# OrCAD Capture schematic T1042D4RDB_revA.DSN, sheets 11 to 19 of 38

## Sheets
11 11 QE: size B
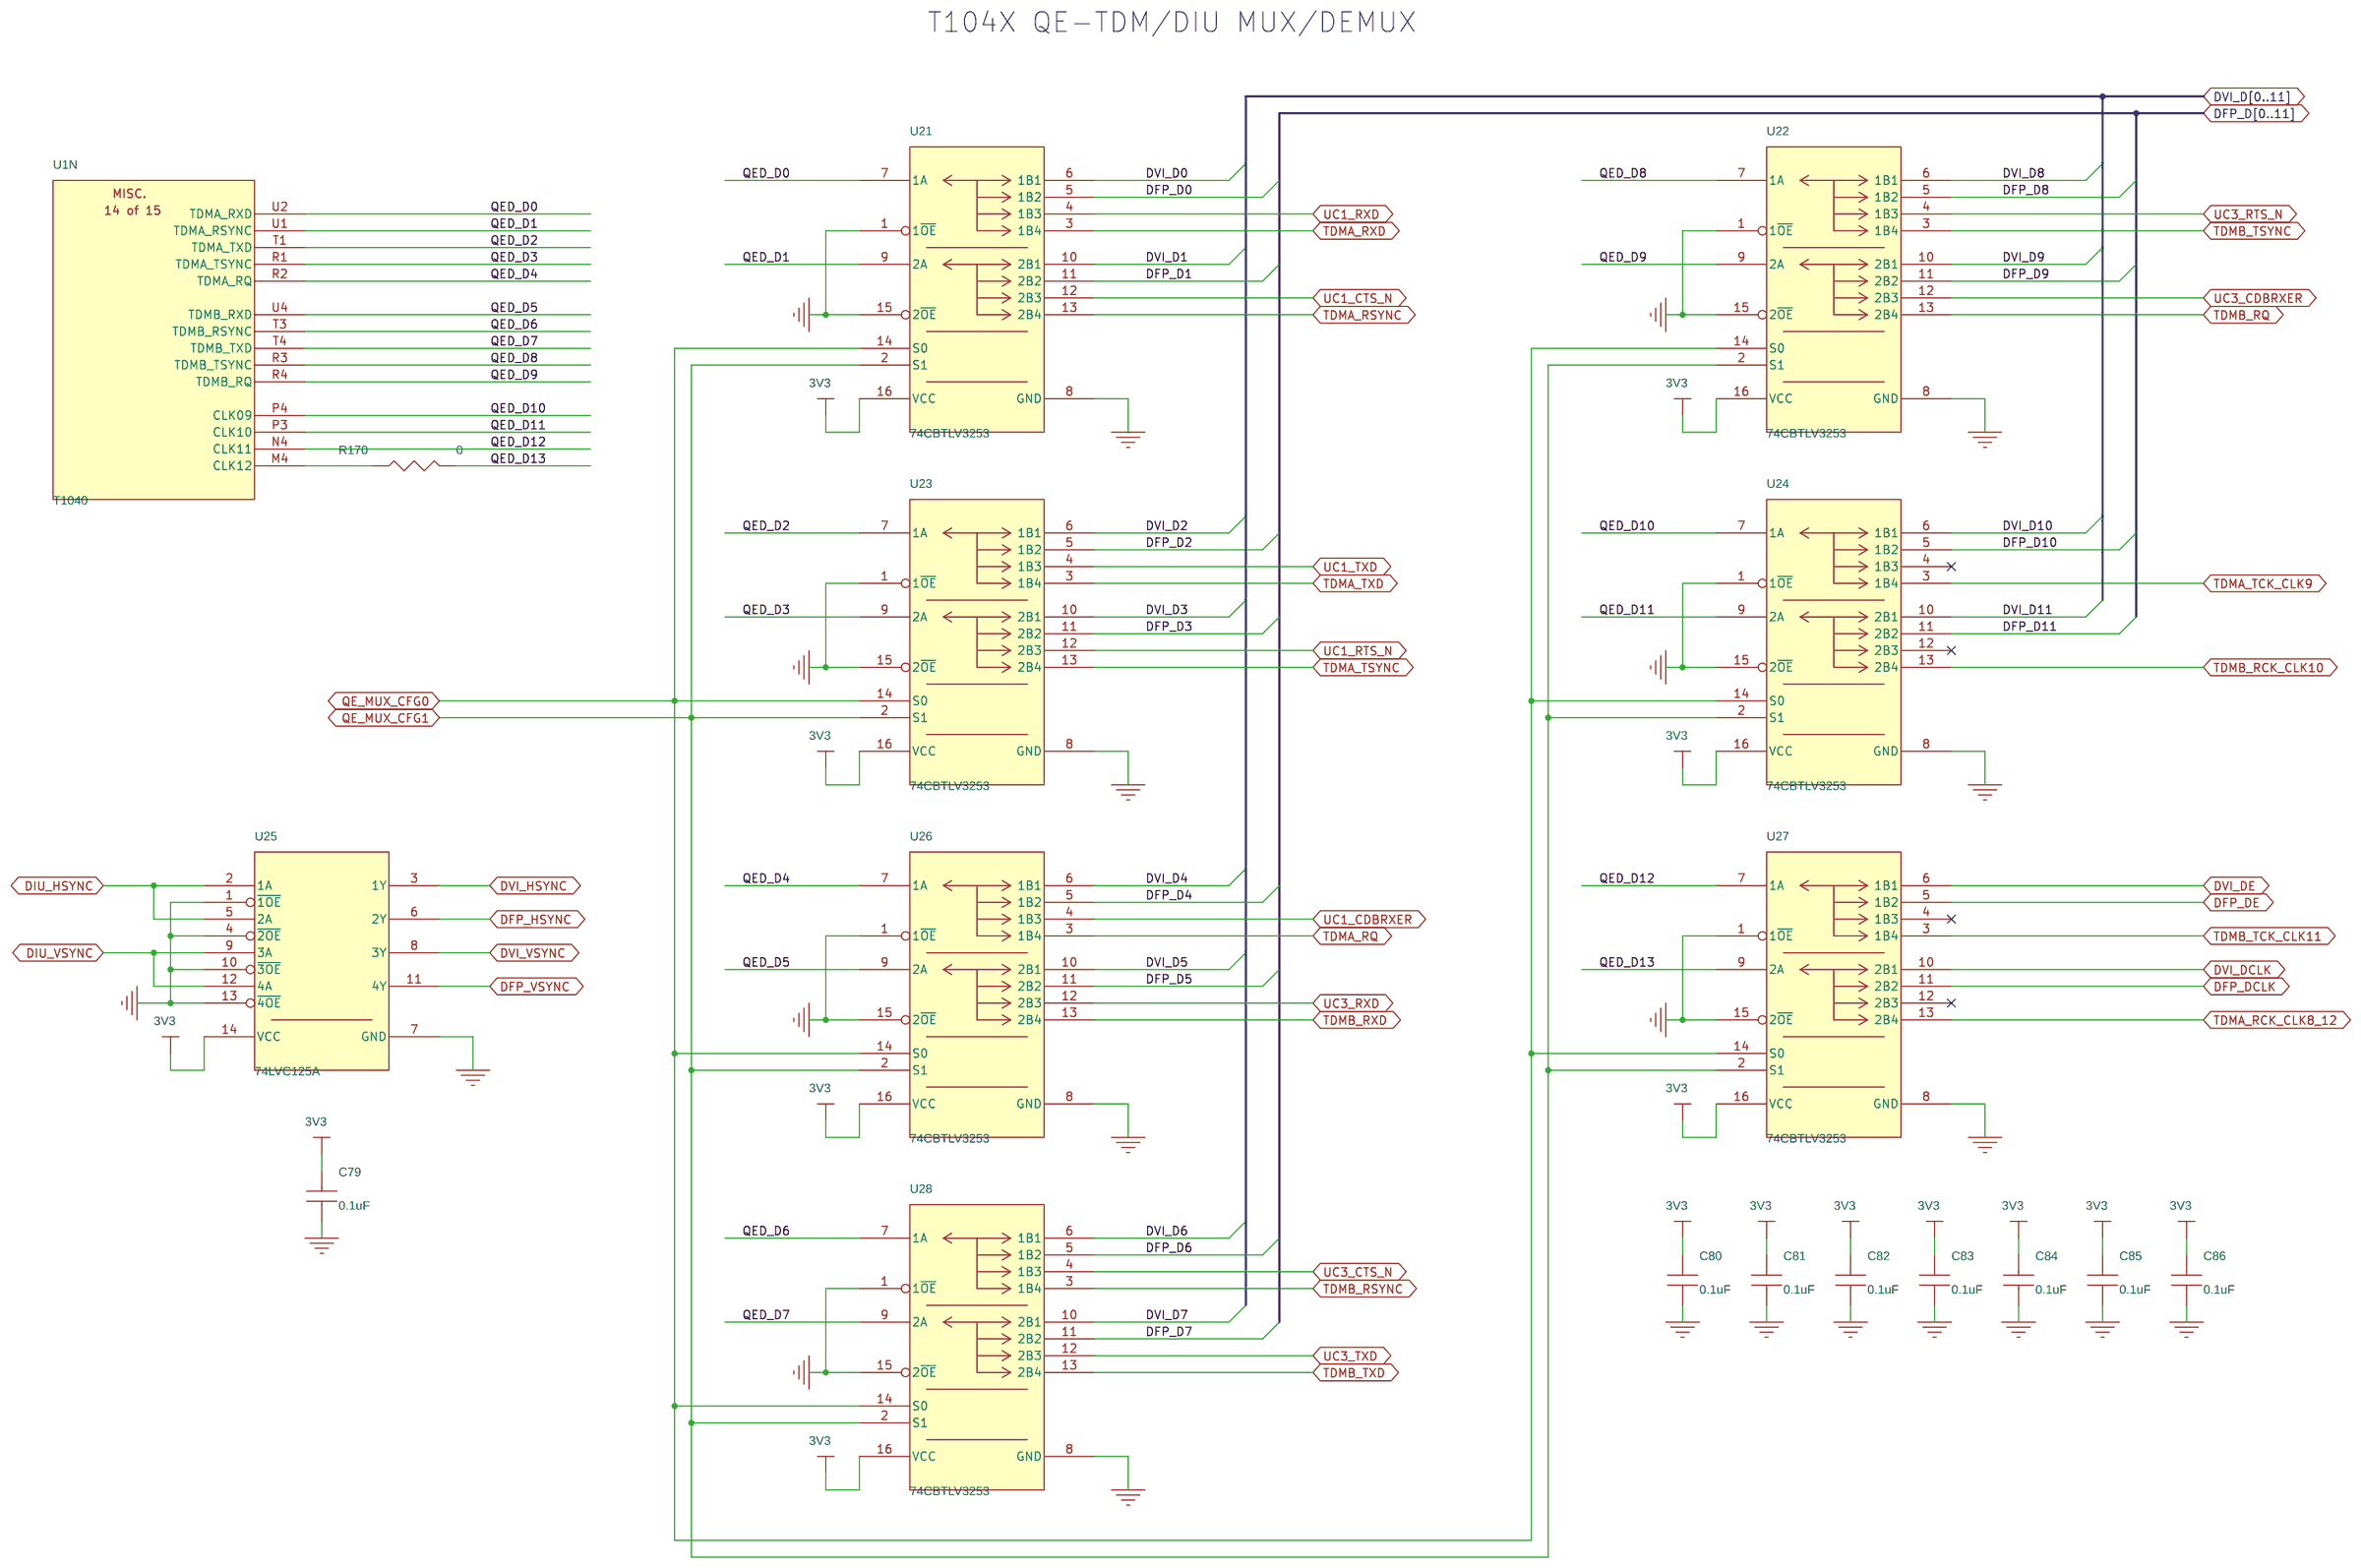
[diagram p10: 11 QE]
12 12 Proc Pwr: size B
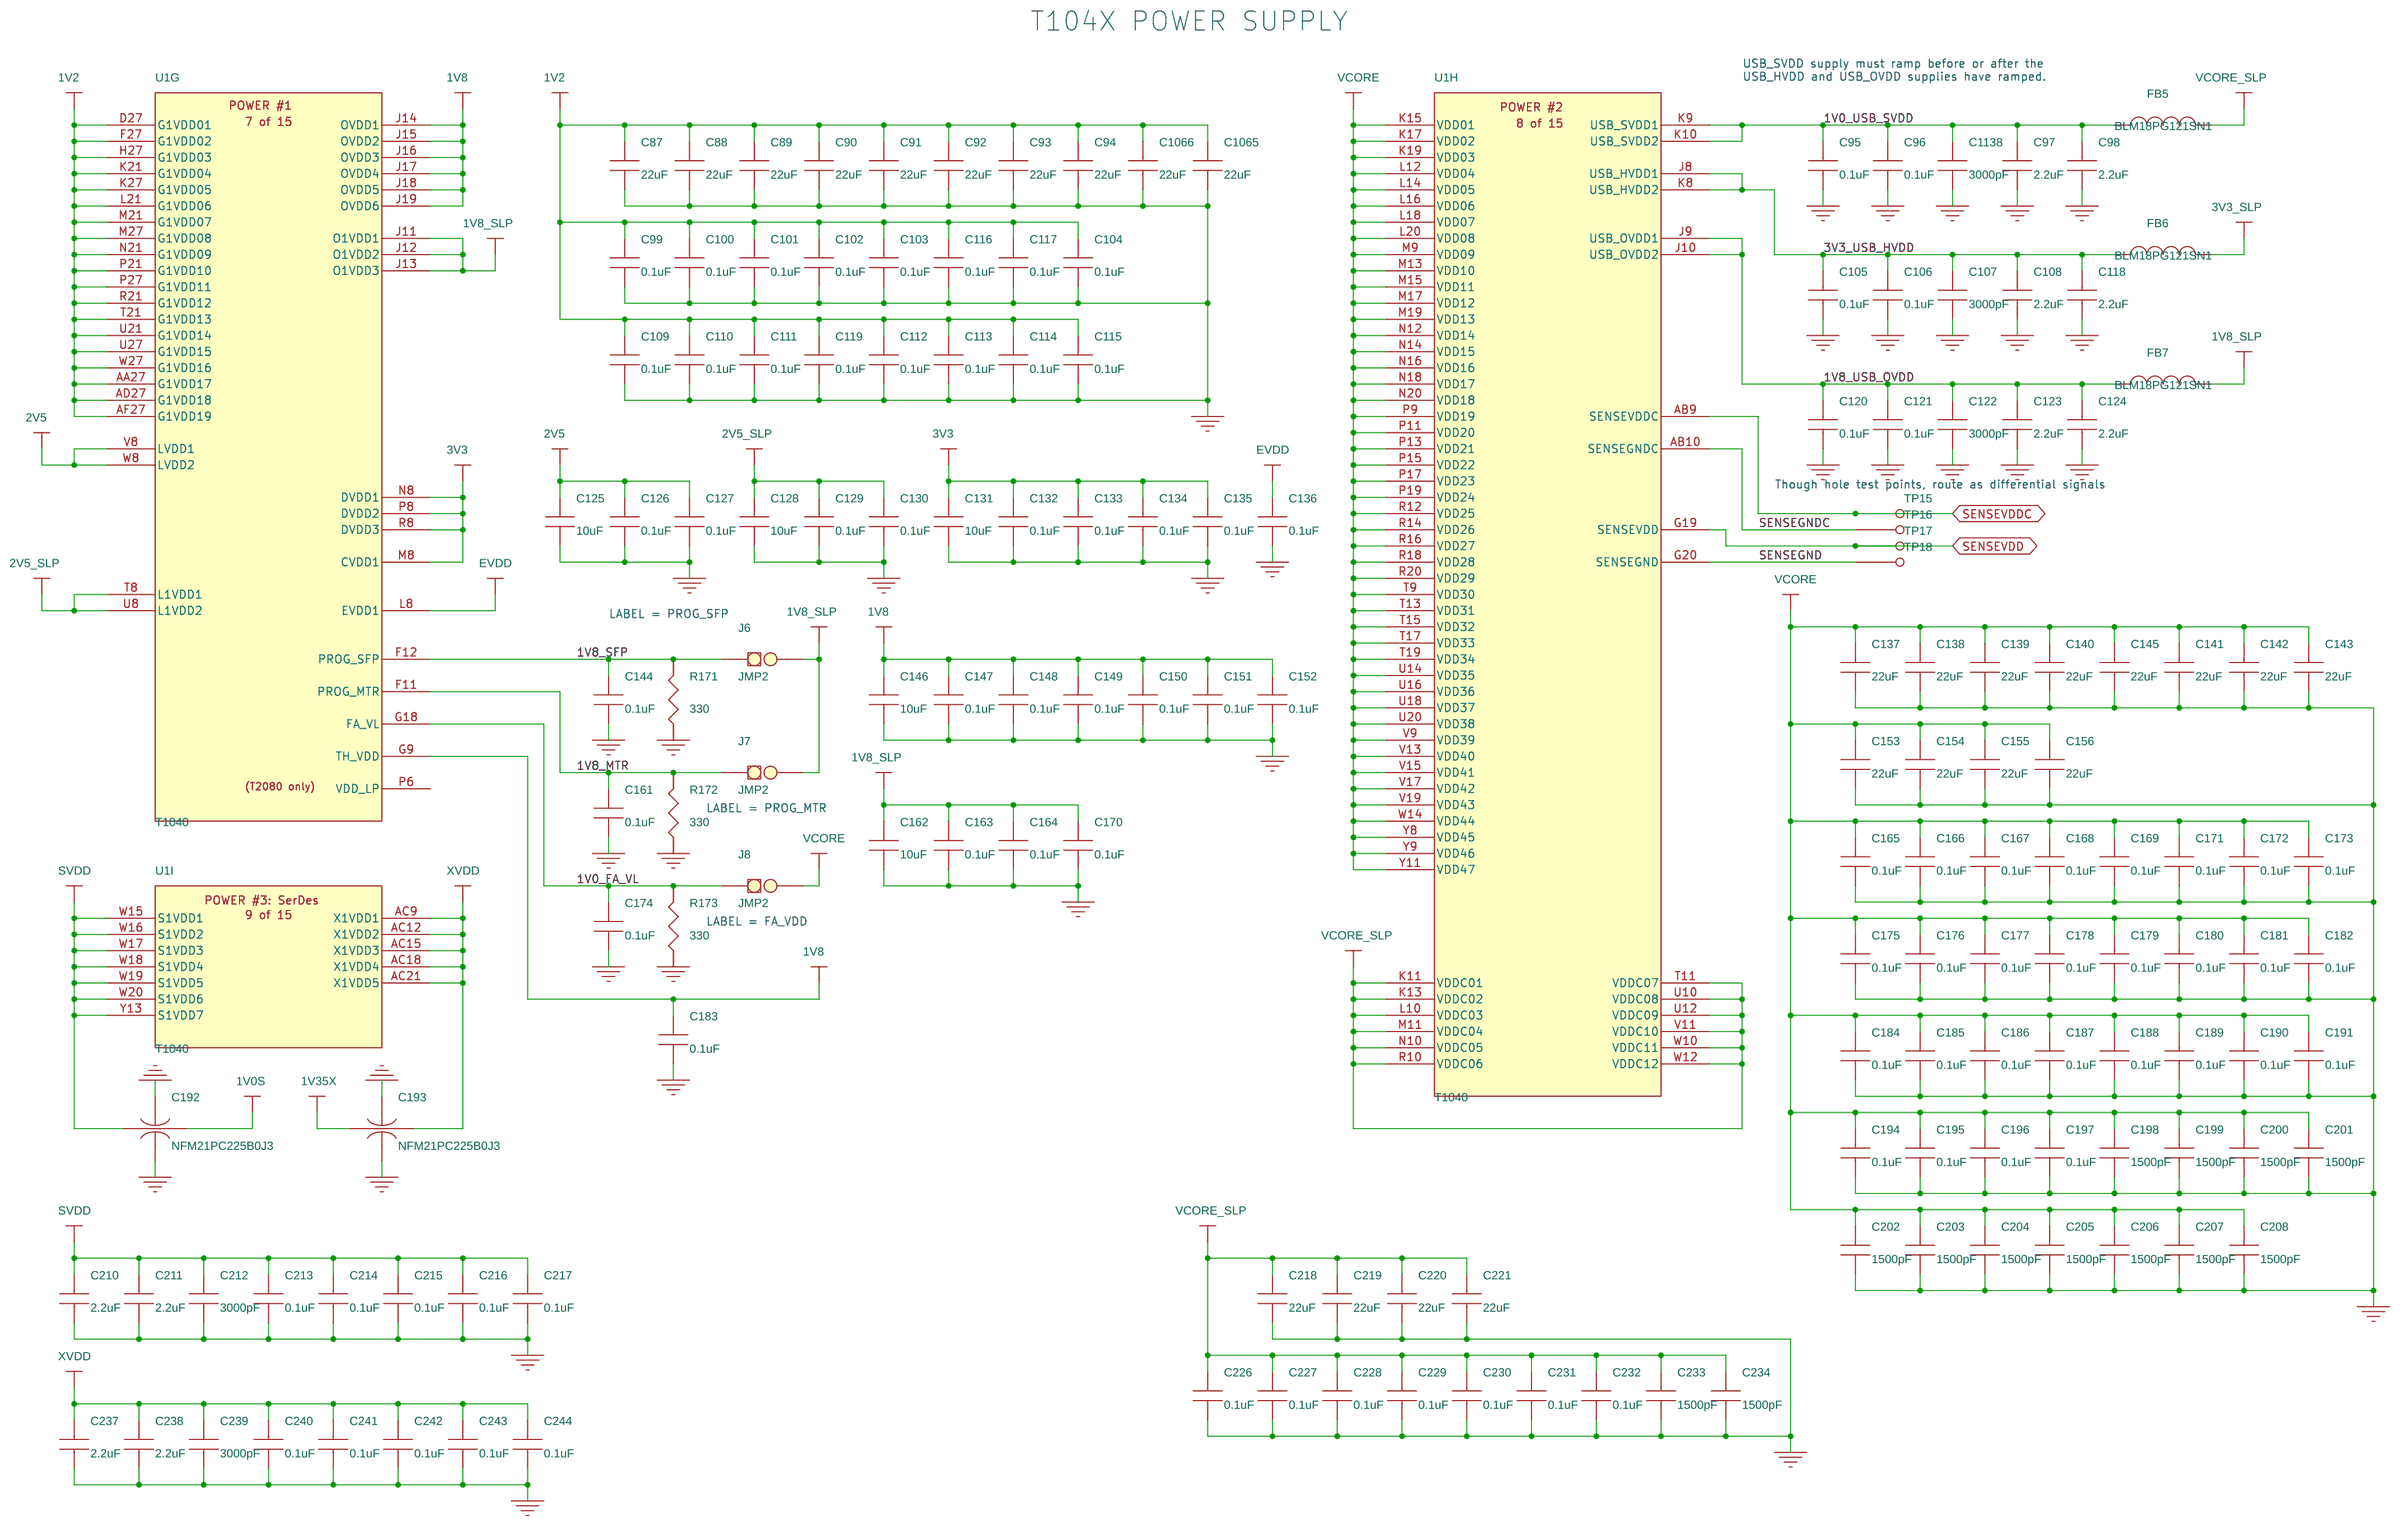
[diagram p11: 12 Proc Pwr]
13 13 Proc Gnd: size B
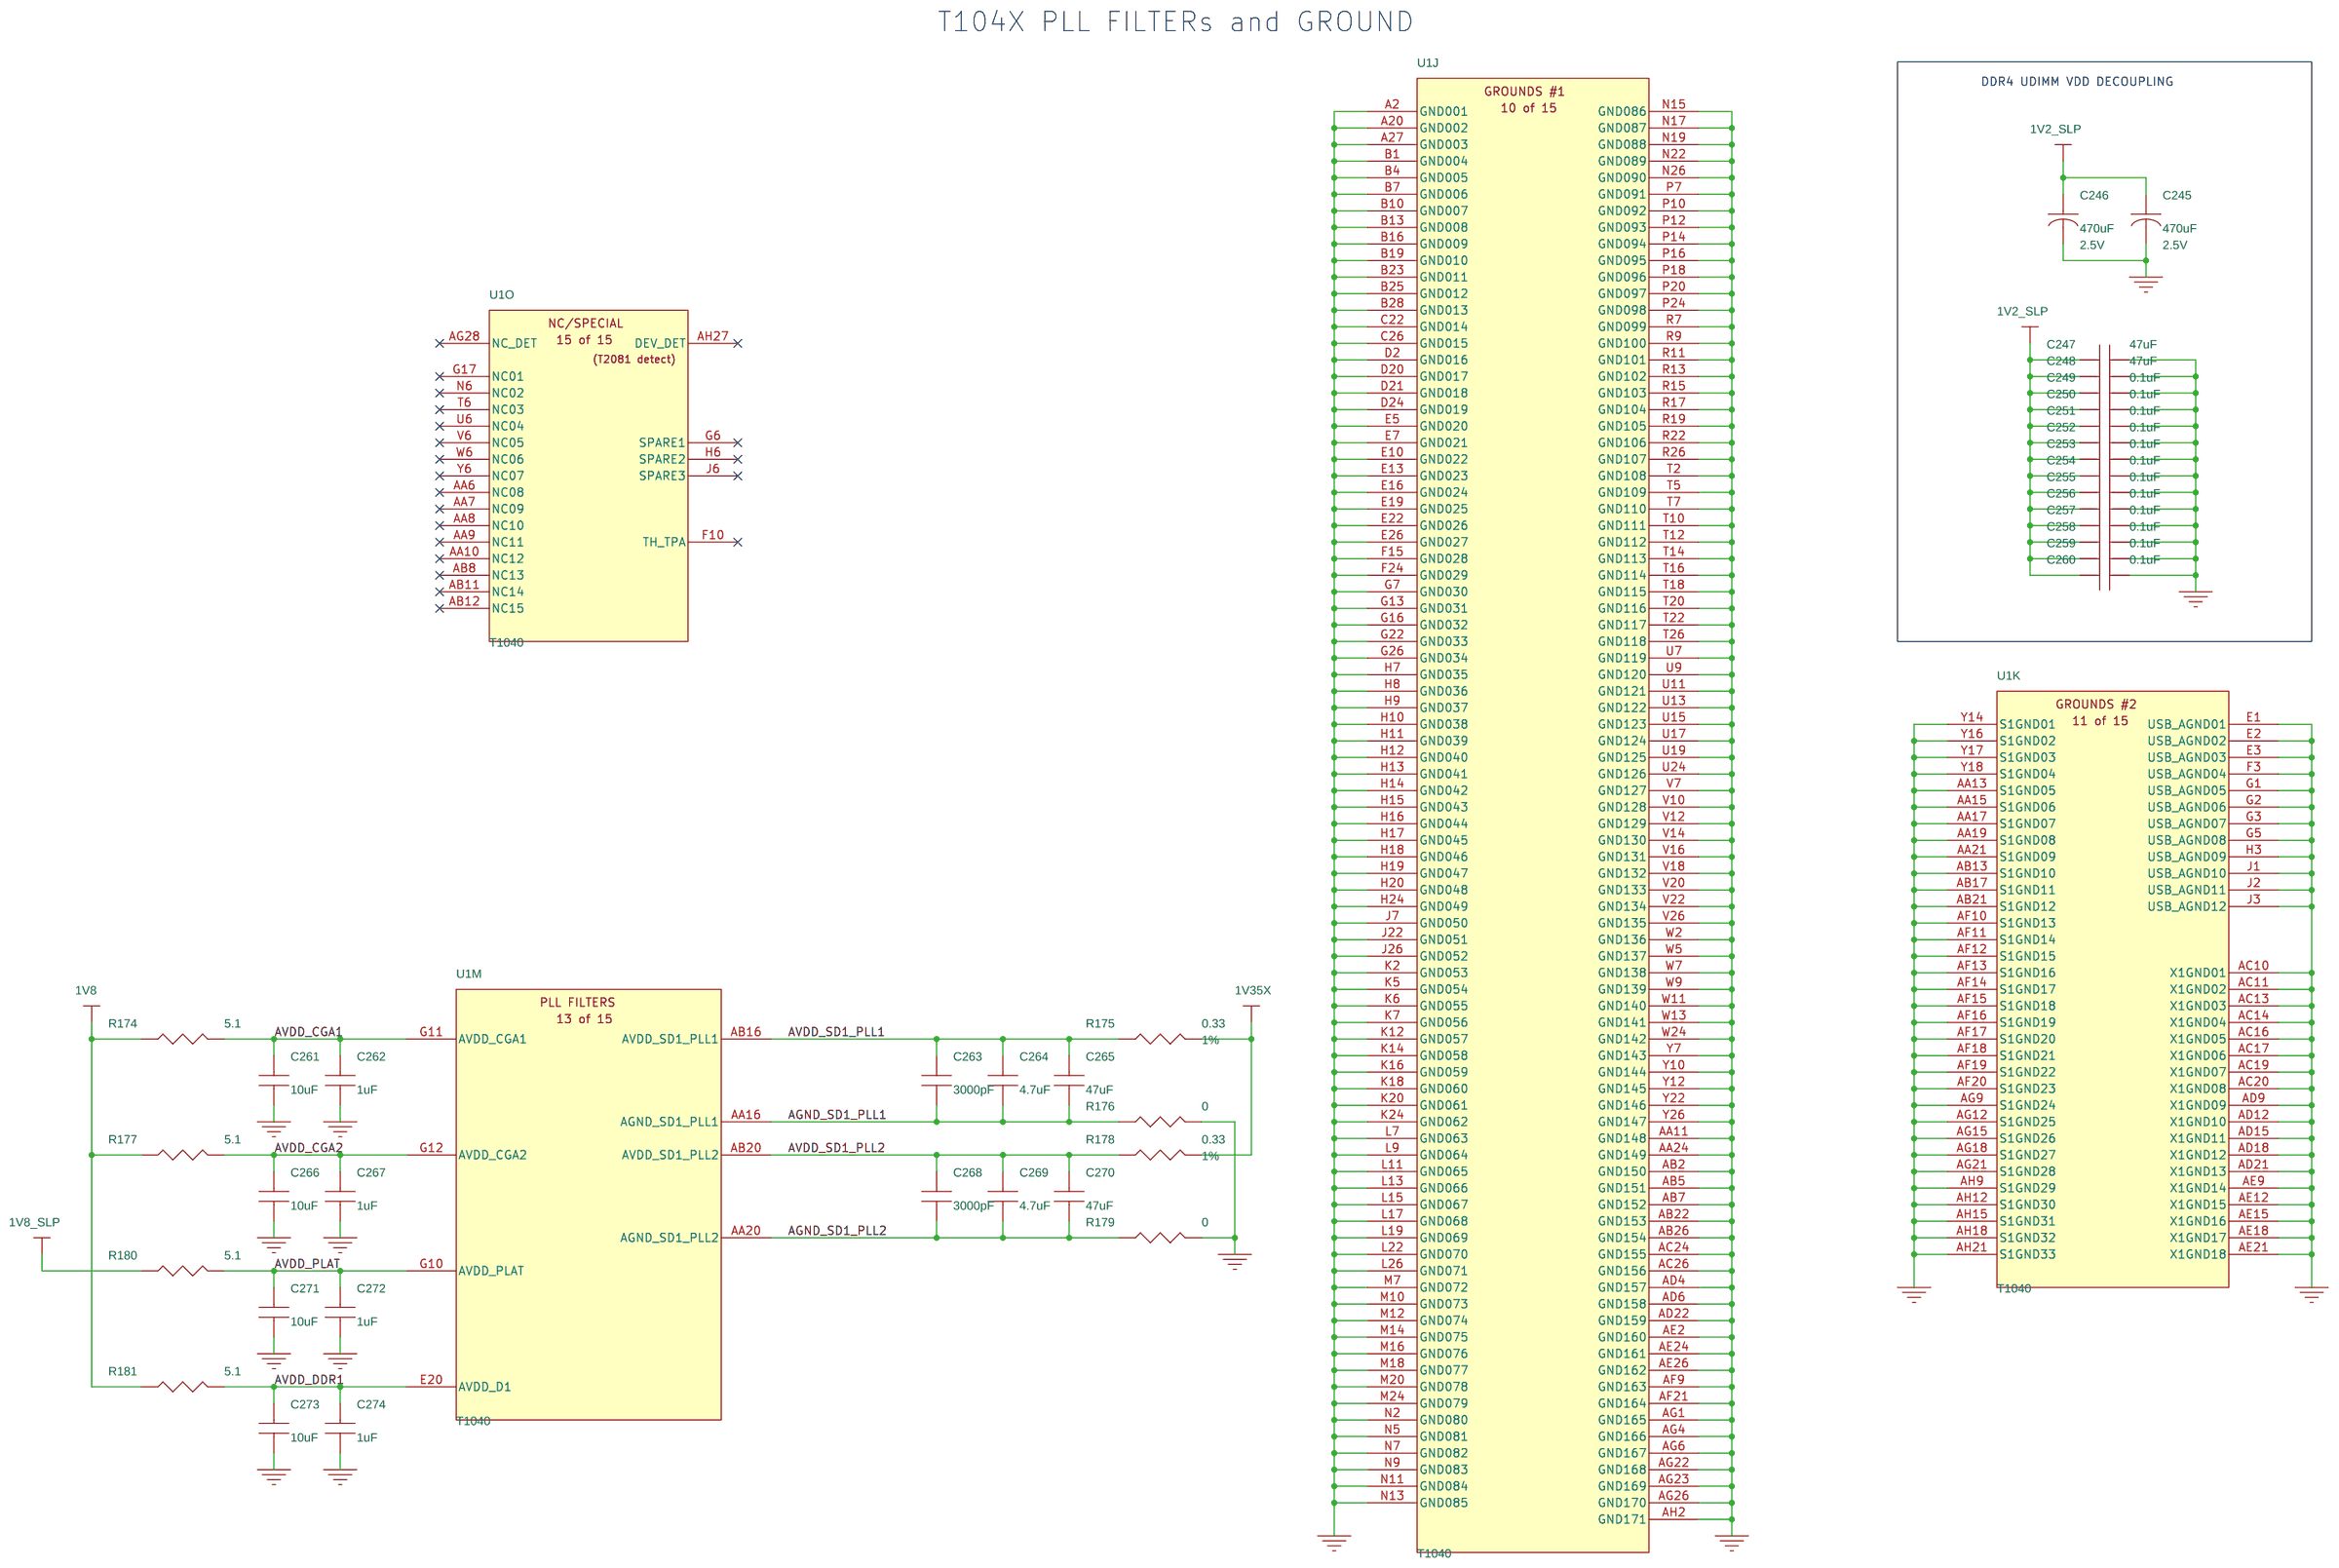
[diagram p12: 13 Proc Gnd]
14 14 UART&I2C: size B
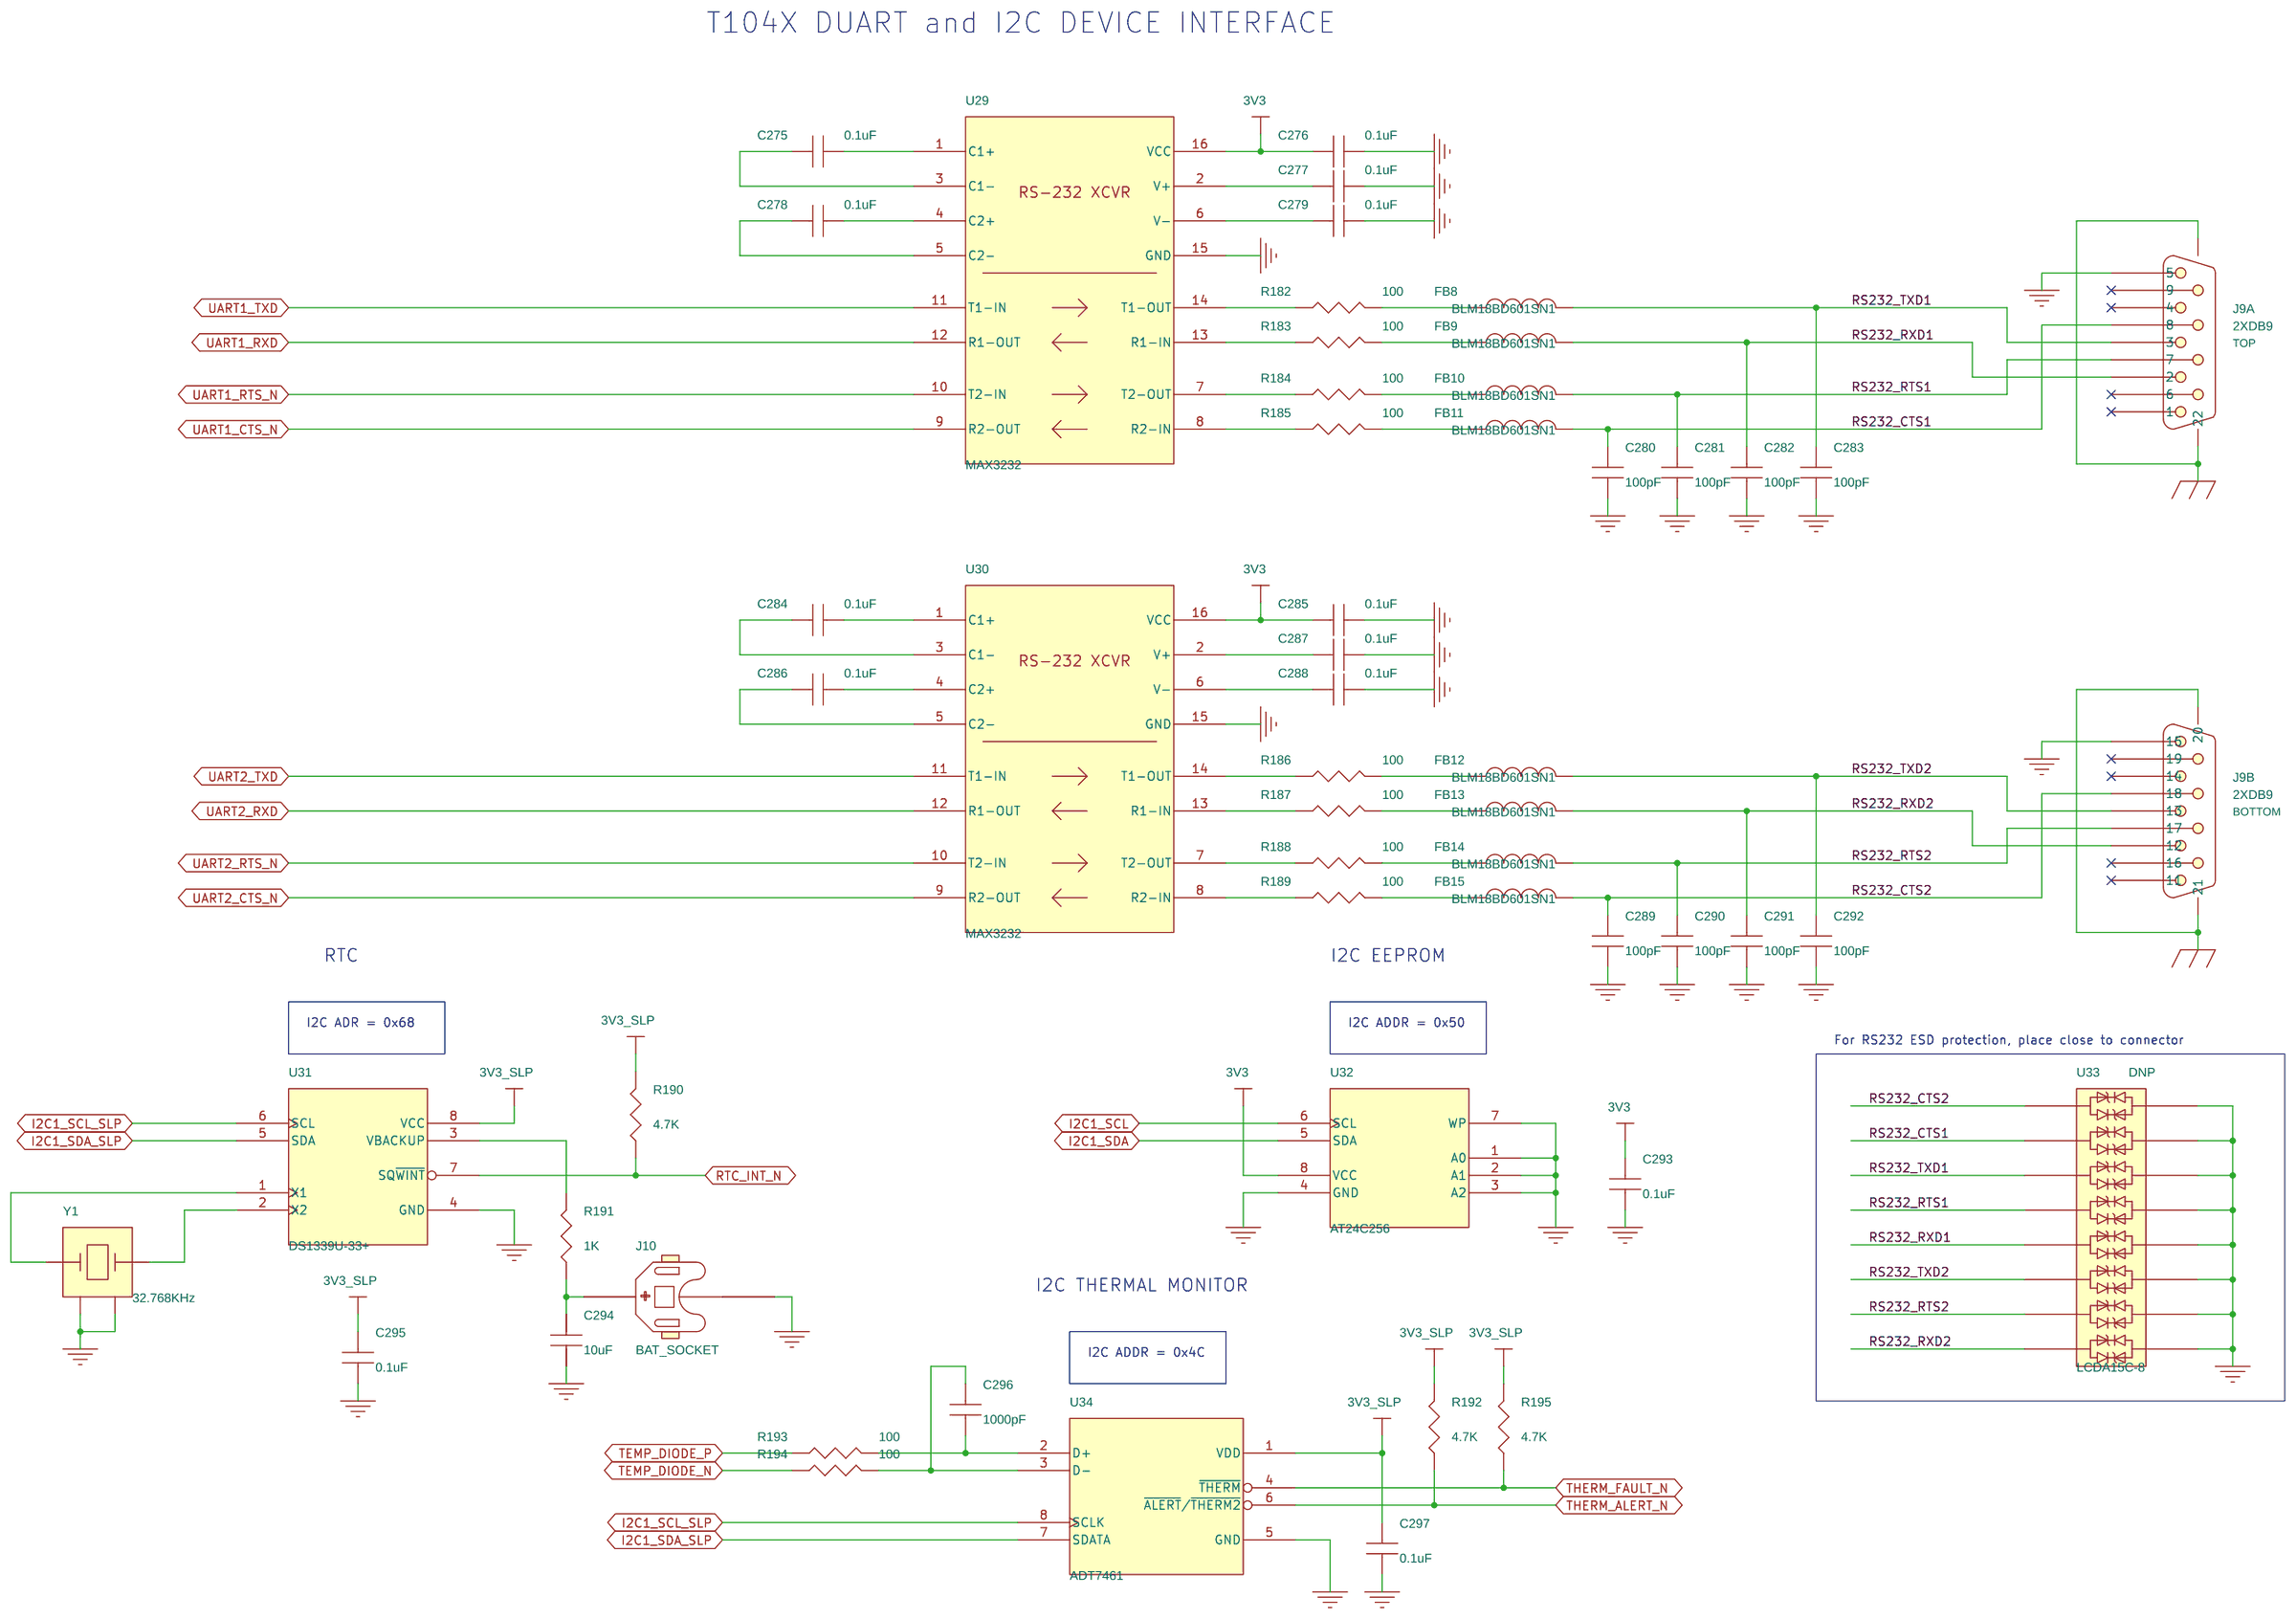
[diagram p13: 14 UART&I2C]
15 15 TDM: size B
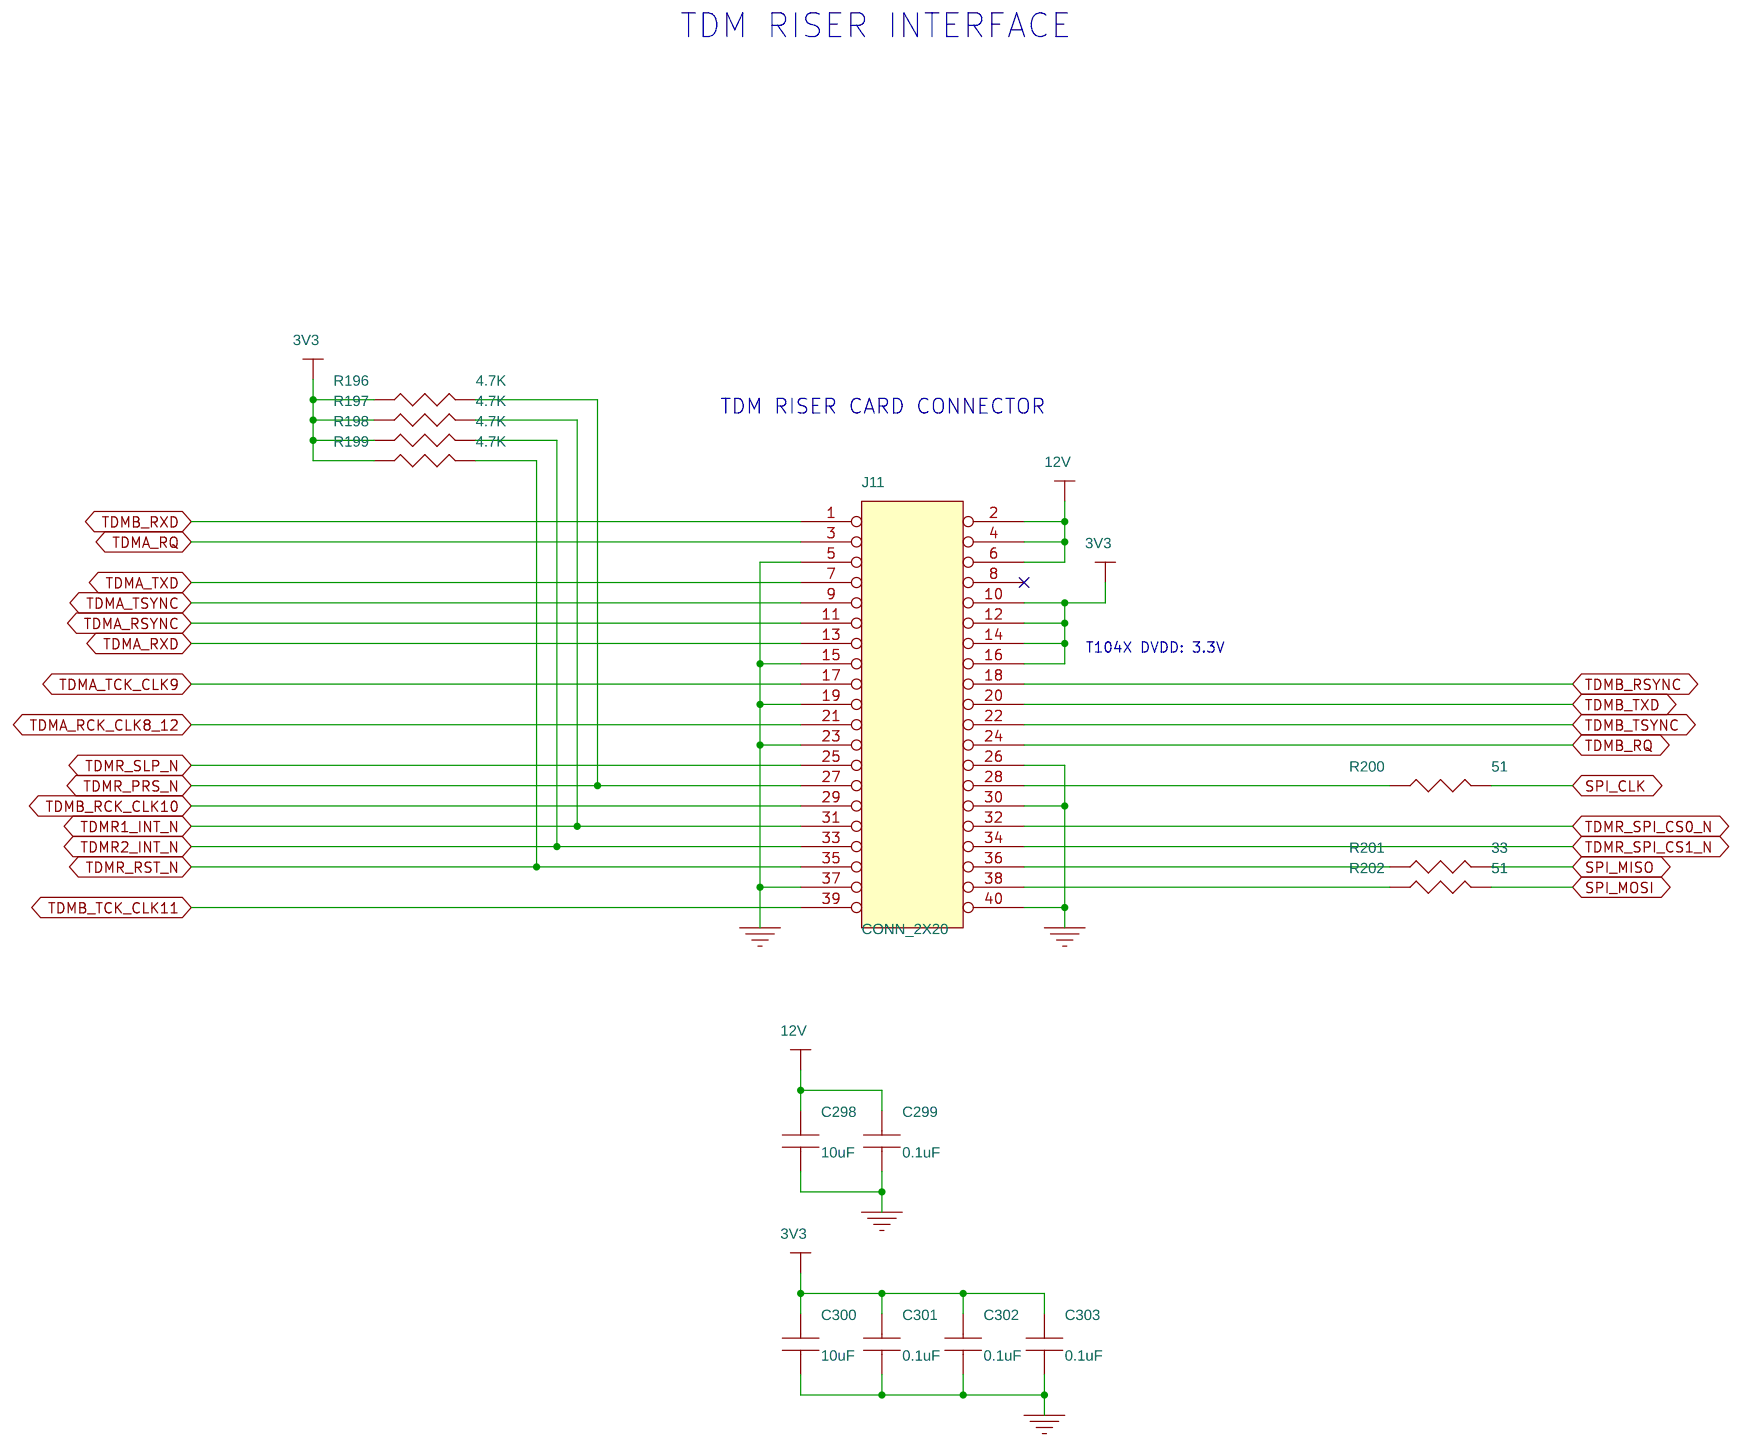
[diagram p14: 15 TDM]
16 16 HDMI: size B
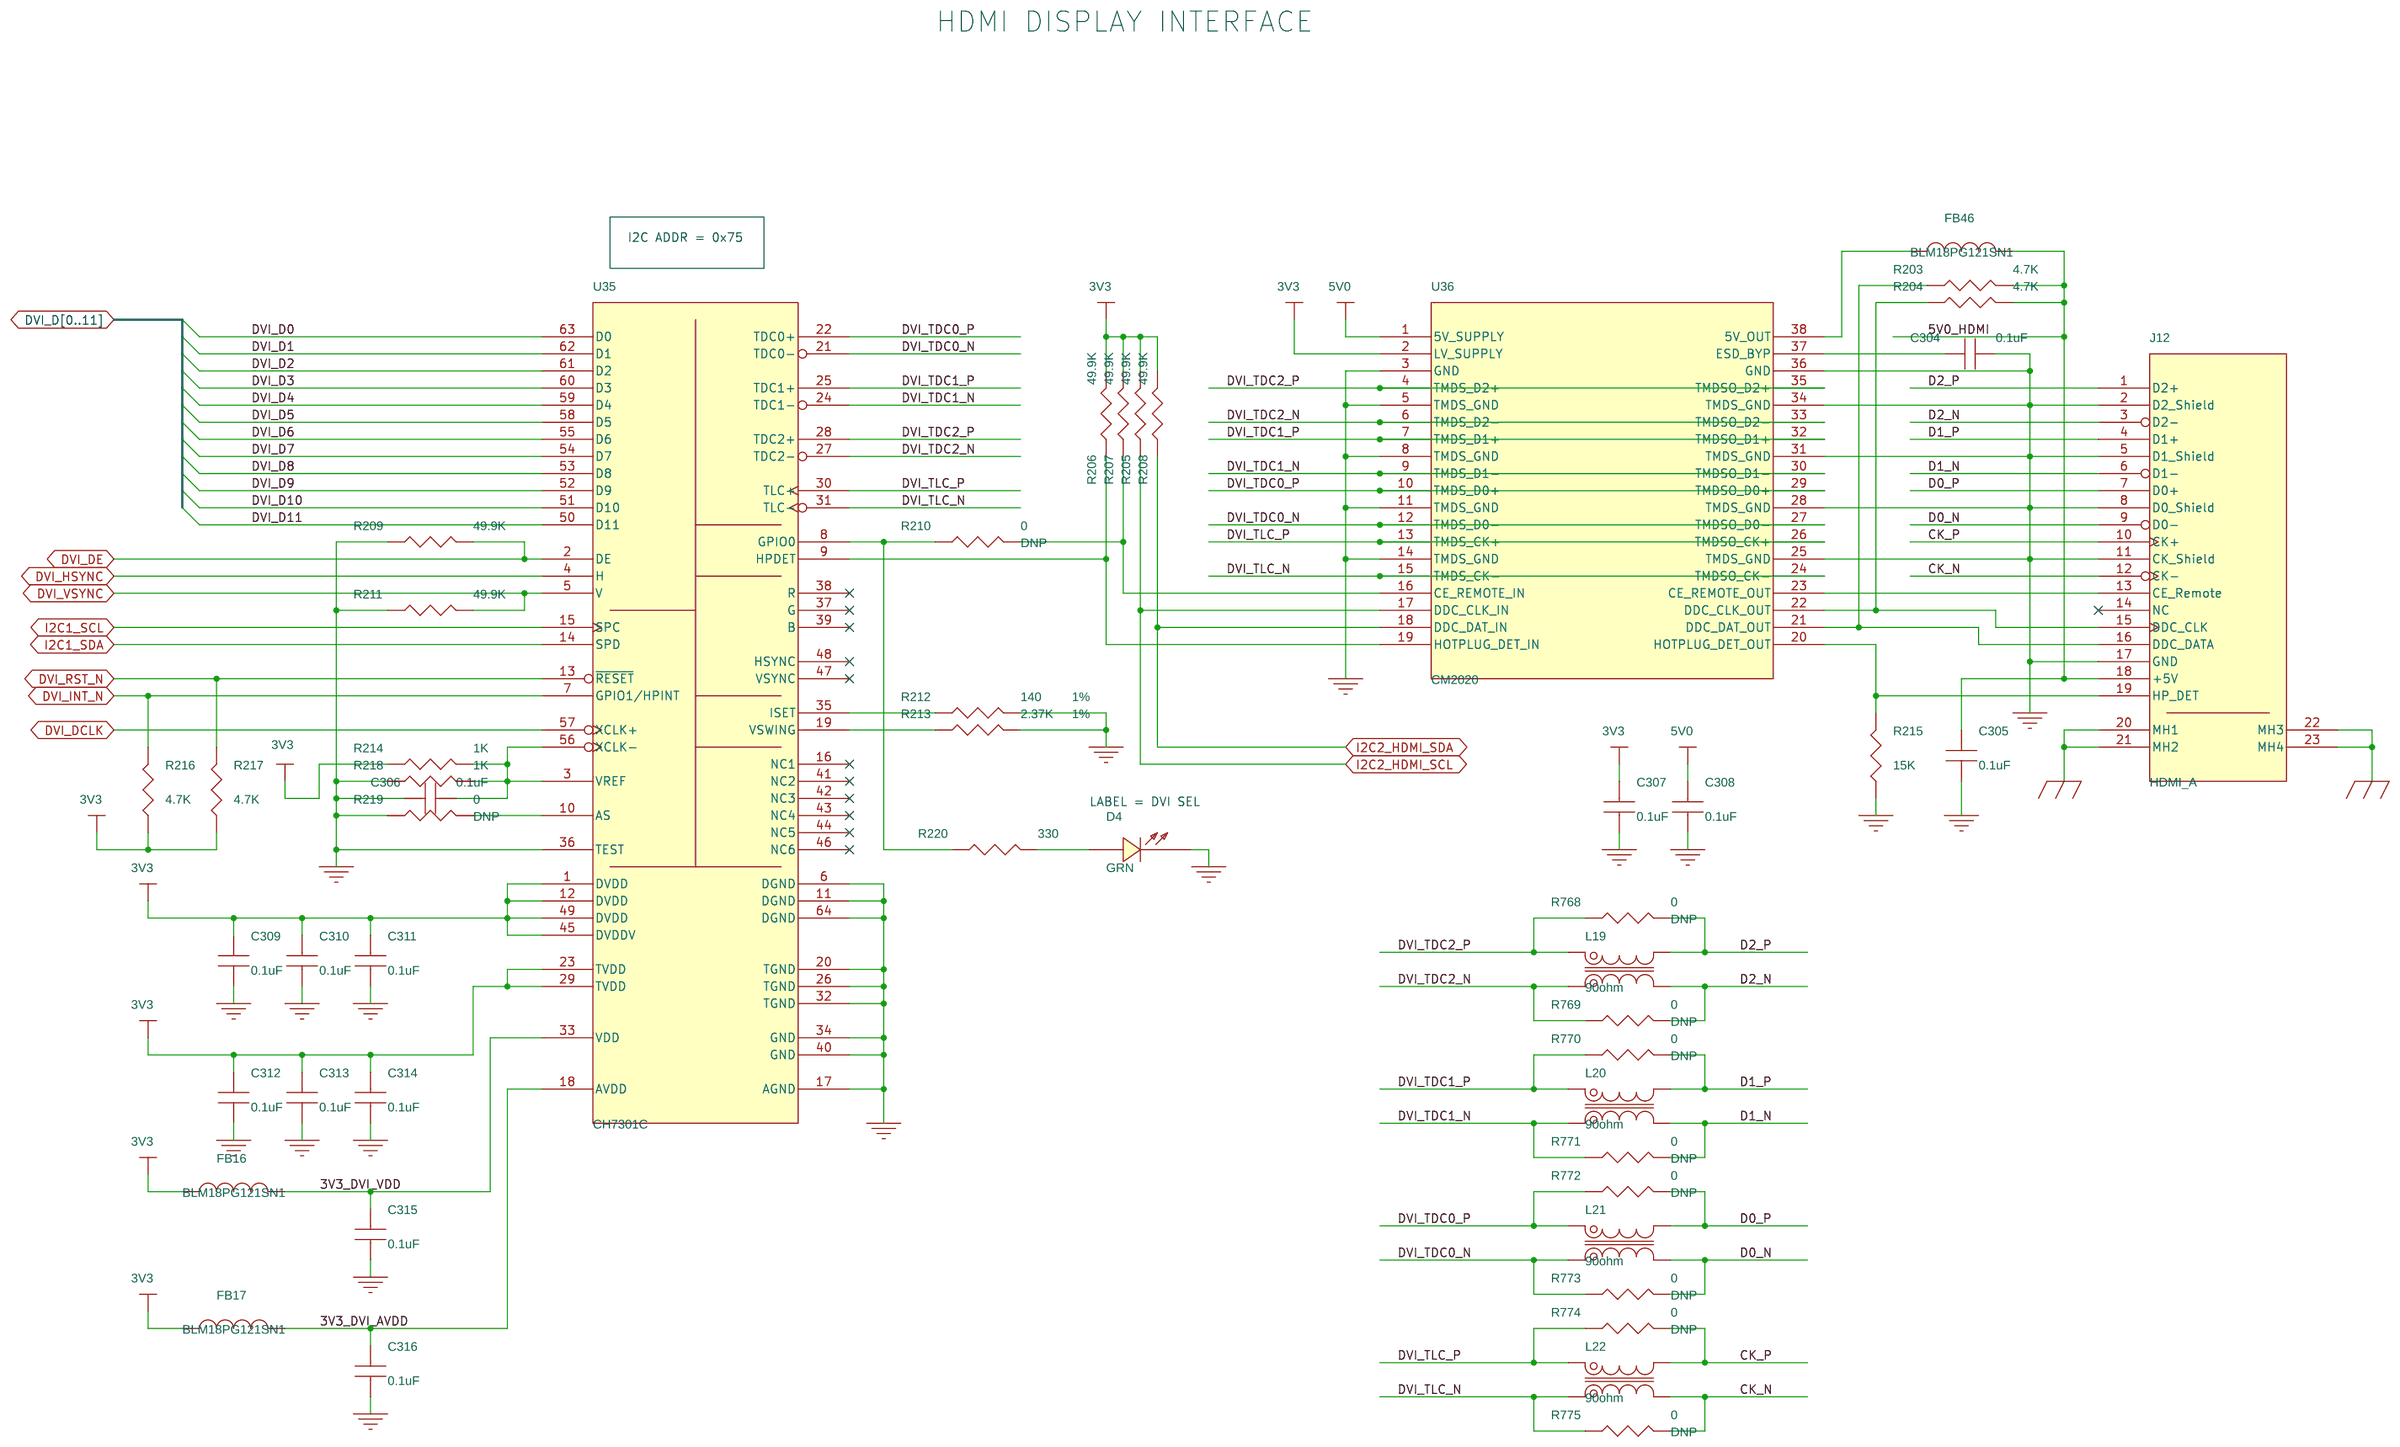
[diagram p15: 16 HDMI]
17 17 LCD: size B
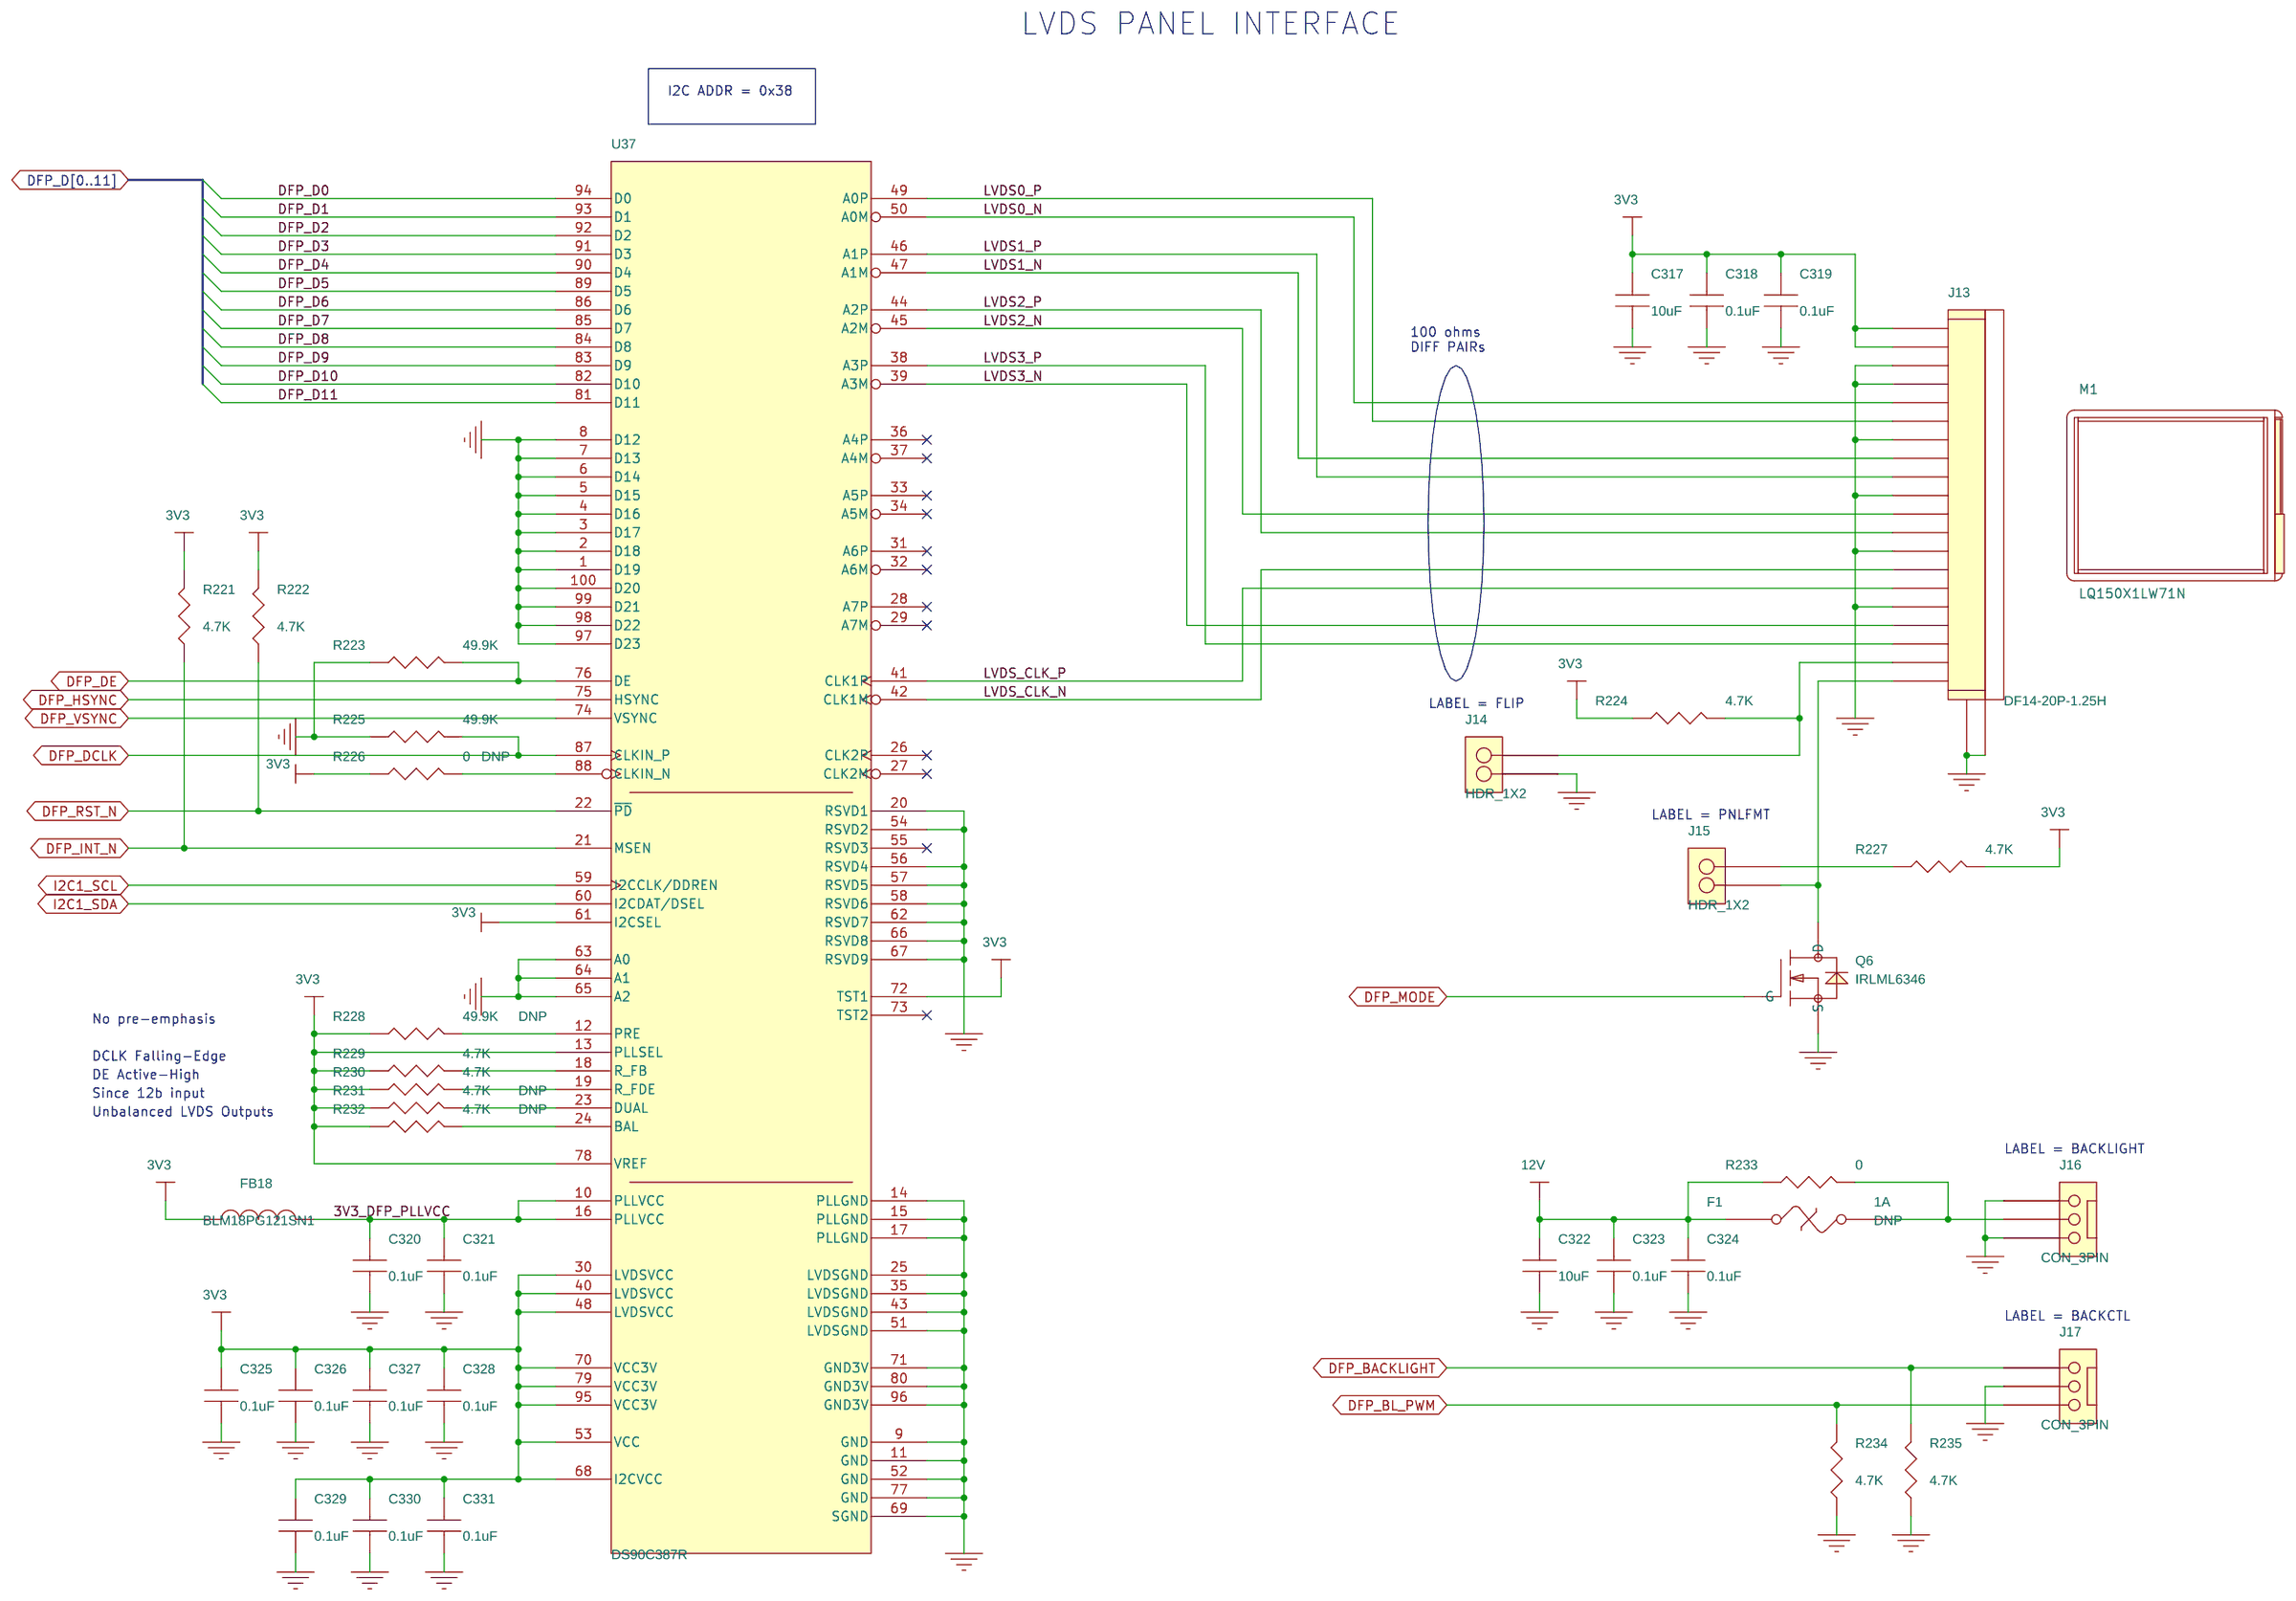
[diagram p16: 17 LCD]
18 18 Profibus: size B
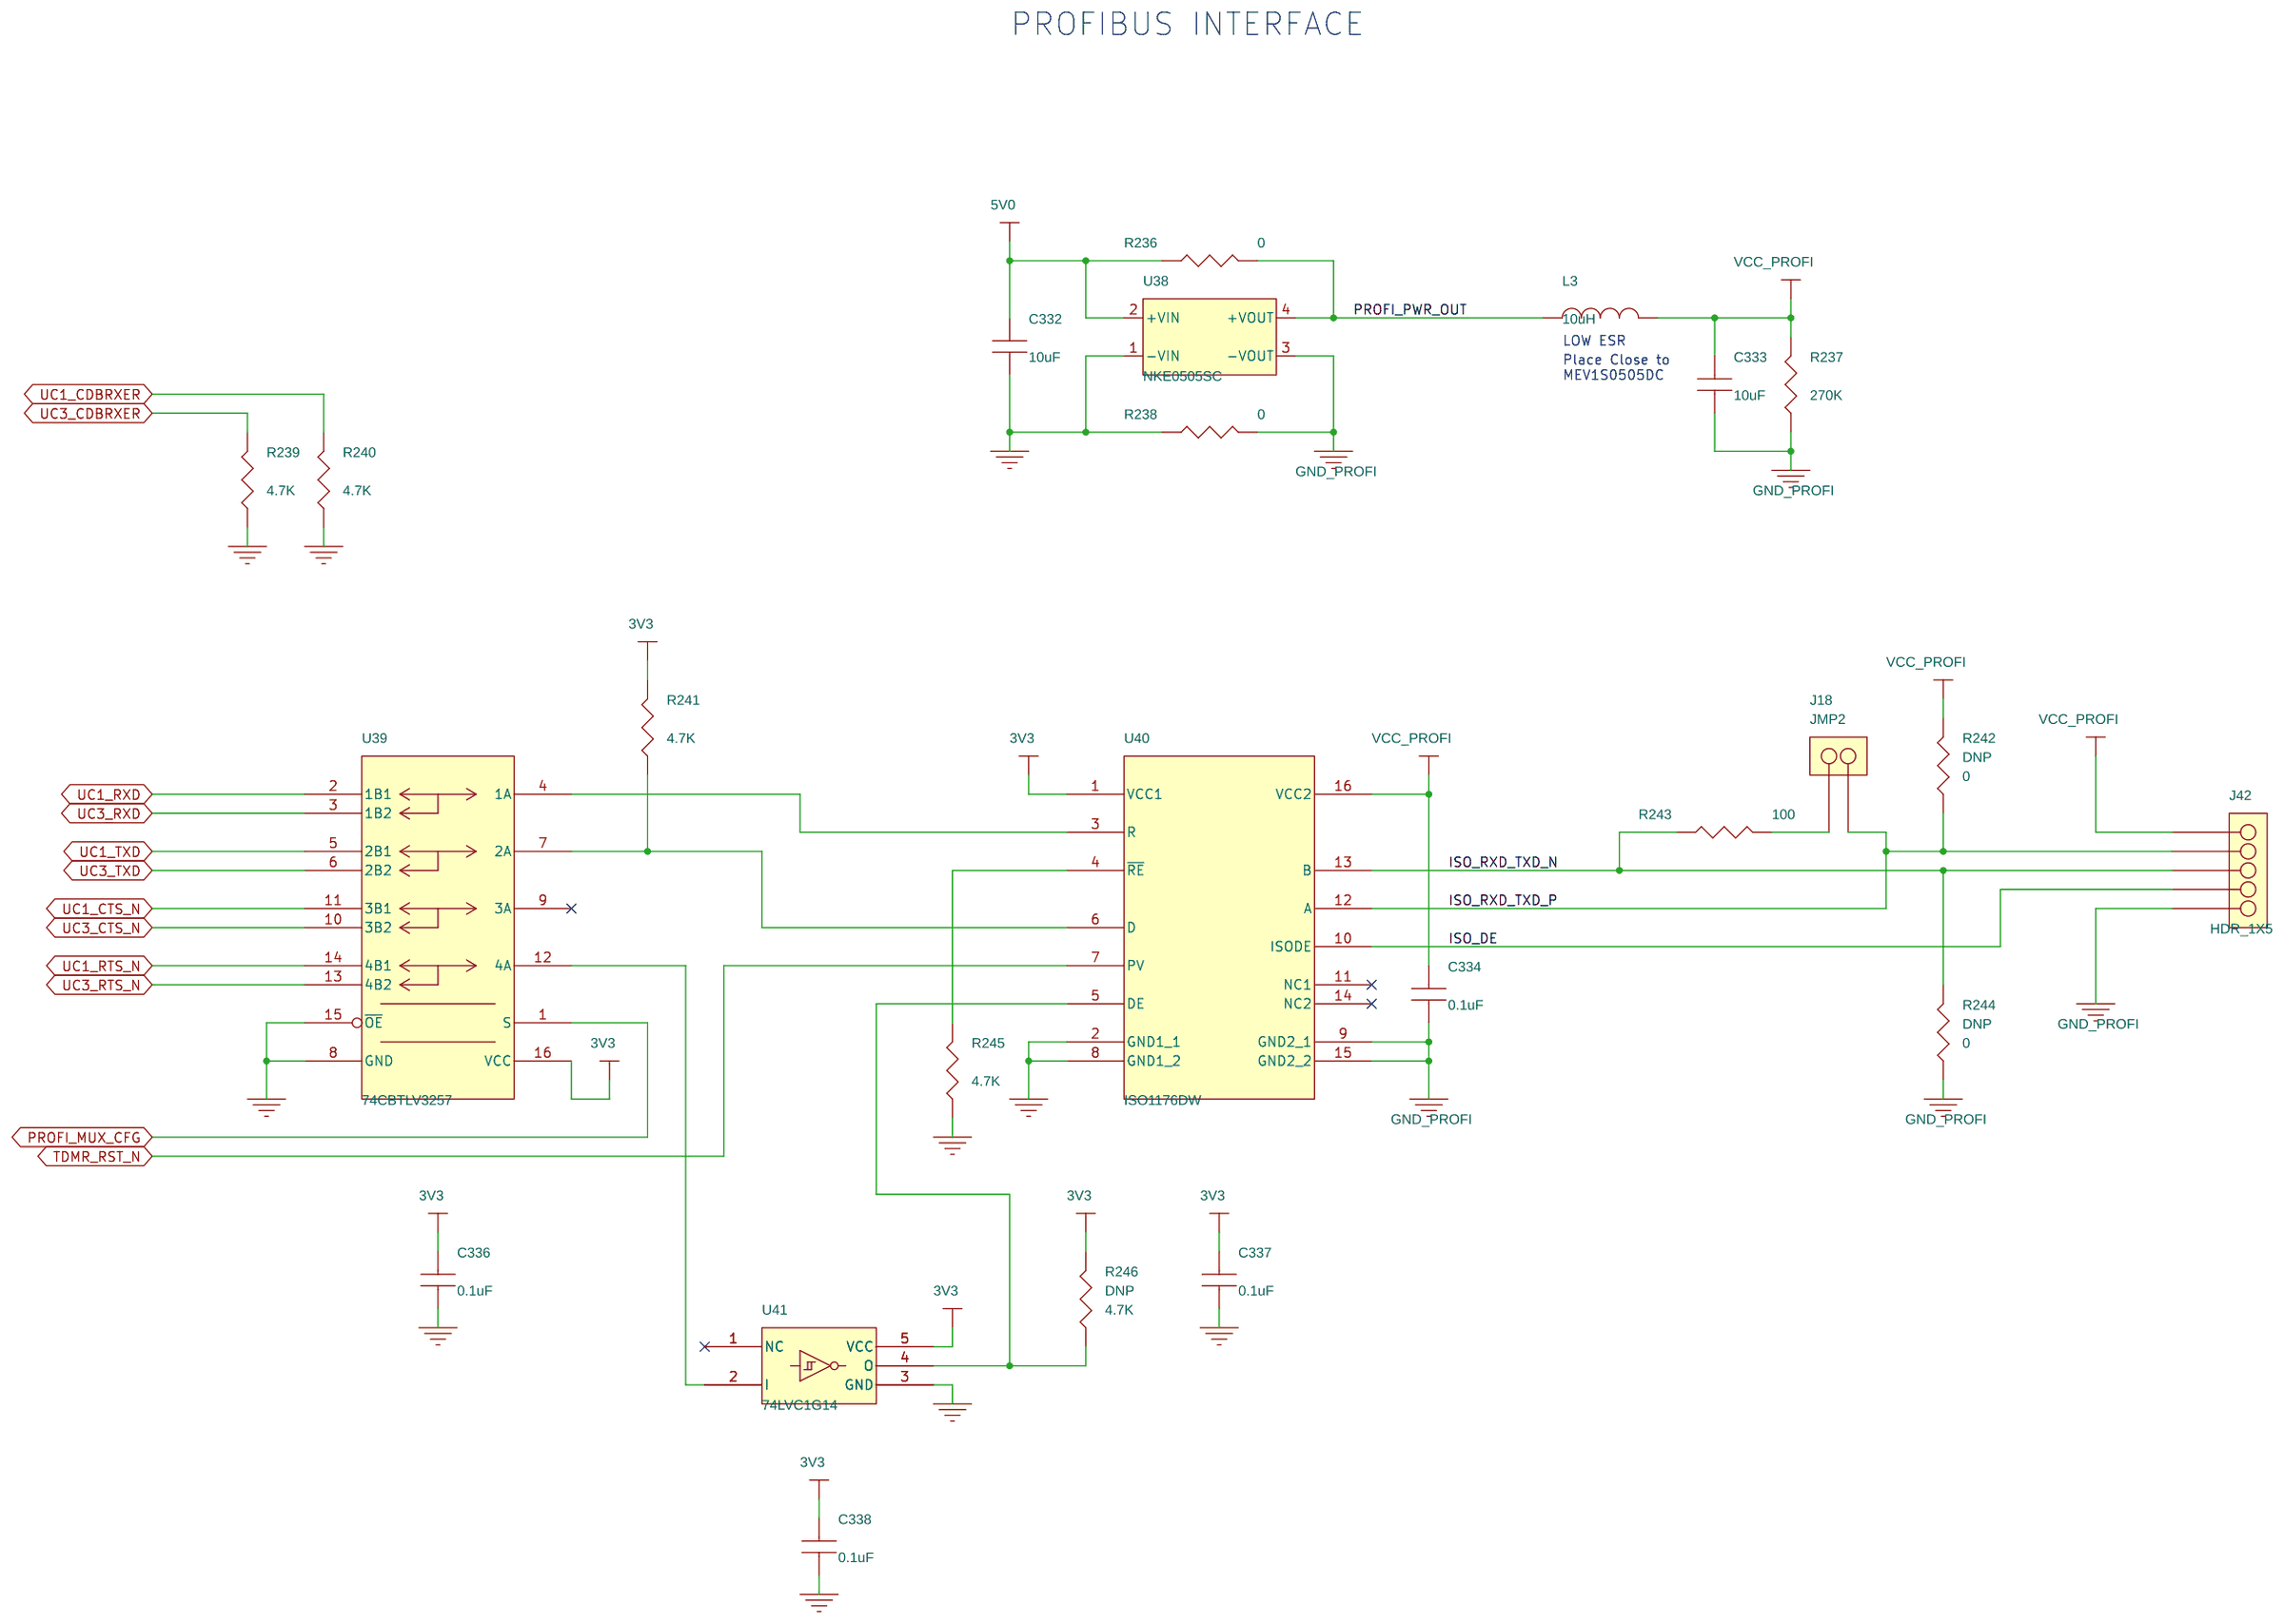
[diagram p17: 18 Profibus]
19 19 EC1 PHY: size B
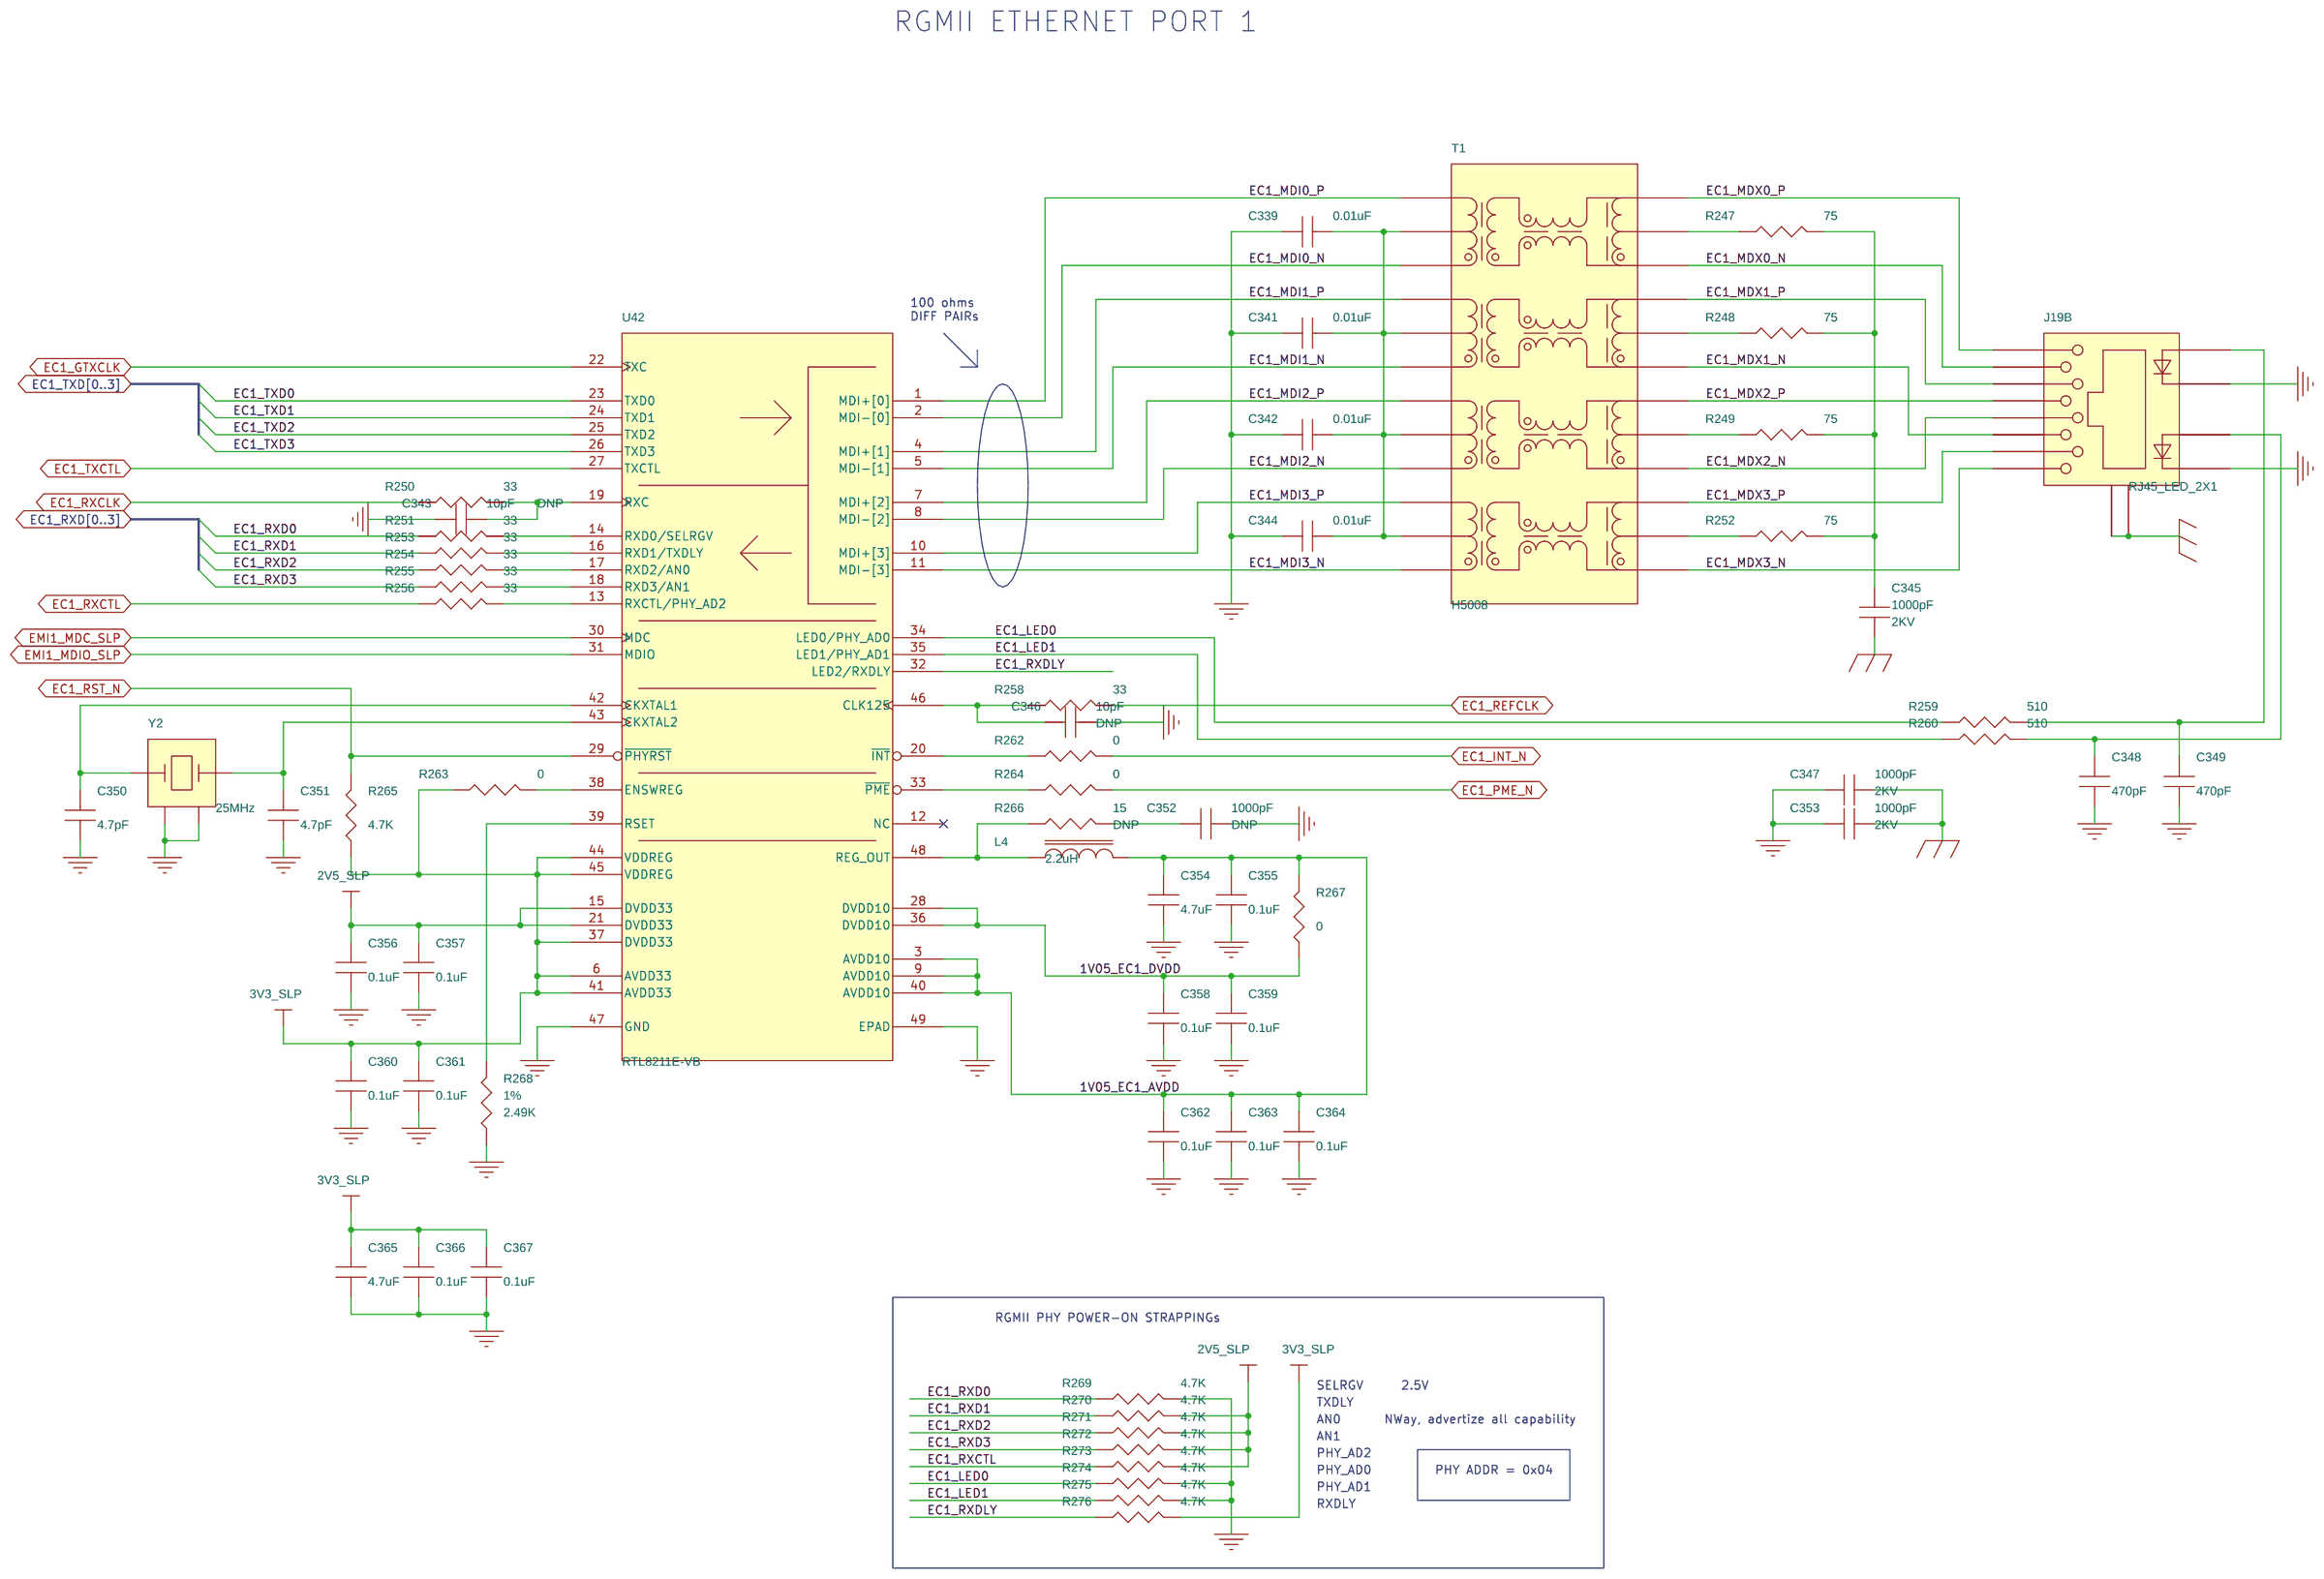
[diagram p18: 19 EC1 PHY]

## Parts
sheet 07 SYS
U1  T1040  [bga_p080_780]  (sections A,B,C,D,E,F,G,H,I,J,K,L,M,N,O)
sheet 11 QE
C79  0.1uF  [0402]
C80  0.1uF  [0402]
C81  0.1uF  [0402]
C82  0.1uF  [0402]
C83  0.1uF  [0402]
C84  0.1uF  [0402]
C85  0.1uF  [0402]
C86  0.1uF  [0402]
R170  0  [0402]
U21  74CBTLV3253  [tssop_16]
U22  74CBTLV3253  [tssop_16]
U23  74CBTLV3253  [tssop_16]
U24  74CBTLV3253  [tssop_16]
U25  74LVC125A  [tssop_14]
U26  74CBTLV3253  [tssop_16]
U27  74CBTLV3253  [tssop_16]
U28  74CBTLV3253  [tssop_16]
sheet 12 Proc Pwr
C87  22uF  [0805]
C88  22uF  [0805]
C89  22uF  [0805]
C90  22uF  [0805]
C91  22uF  [0805]
C92  22uF  [0805]
C93  22uF  [0805]
C94  22uF  [0805]
C95  0.1uF  [0201]
C96  0.1uF  [0201]
C97  2.2uF  [0402]
C98  2.2uF  [0402]
C99  0.1uF  [0201]
C100  0.1uF  [0201]
C101  0.1uF  [0201]
C102  0.1uF  [0201]
C103  0.1uF  [0201]
C104  0.1uF  [0201]
C105  0.1uF  [0201]
C106  0.1uF  [0201]
C107  3000pF  [0402]
C108  2.2uF  [0402]
C109  0.1uF  [0201]
C110  0.1uF  [0201]
C111  0.1uF  [0201]
C112  0.1uF  [0201]
C113  0.1uF  [0201]
C114  0.1uF  [0201]
C115  0.1uF  [0201]
C116  0.1uF  [0201]
C117  0.1uF  [0201]
C118  2.2uF  [0402]
C119  0.1uF  [0201]
C120  0.1uF  [0201]
C121  0.1uF  [0201]
C122  3000pF  [0402]
C123  2.2uF  [0402]
C124  2.2uF  [0402]
C125  10uF  [0603]
C126  0.1uF  [0201]
C127  0.1uF  [0201]
C128  10uF  [0603]
C129  0.1uF  [0201]
C130  0.1uF  [0201]
C131  10uF  [0603]
C132  0.1uF  [0201]
C133  0.1uF  [0201]
C134  0.1uF  [0201]
C135  0.1uF  [0201]
C136  0.1uF  [0201]
C137  22uF  [0805]
C138  22uF  [0805]
C139  22uF  [0805]
C140  22uF  [0805]
C141  22uF  [0805]
C142  22uF  [0805]
C143  22uF  [0805]
C144  0.1uF  [0201]
C145  22uF  [0805]
C146  10uF  [0603]
C147  0.1uF  [0201]
C148  0.1uF  [0201]
C149  0.1uF  [0201]
C150  0.1uF  [0201]
C151  0.1uF  [0201]
C152  0.1uF  [0201]
C153  22uF  [0805]
C154  22uF  [0805]
C155  22uF  [0805]
C156  22uF  [0805]
C161  0.1uF  [0201]
C162  10uF  [0603]
C163  0.1uF  [0201]
C164  0.1uF  [0201]
C165  0.1uF  [0201]
C166  0.1uF  [0201]
C167  0.1uF  [0201]
C168  0.1uF  [0201]
C169  0.1uF  [0201]
C170  0.1uF  [0201]
C171  0.1uF  [0201]
C172  0.1uF  [0201]
C173  0.1uF  [0201]
C174  0.1uF  [0201]
C175  0.1uF  [0201]
C176  0.1uF  [0201]
C177  0.1uF  [0201]
C178  0.1uF  [0201]
C179  0.1uF  [0201]
C180  0.1uF  [0201]
C181  0.1uF  [0201]
C182  0.1uF  [0201]
C183  0.1uF  [0201]
C184  0.1uF  [0201]
C185  0.1uF  [0201]
C186  0.1uF  [0201]
C187  0.1uF  [0201]
C188  0.1uF  [0201]
C189  0.1uF  [0201]
C190  0.1uF  [0201]
C191  0.1uF  [0201]
C192  NFM21PC225B0J3  [nfm21]
C193  NFM21PC225B0J3  [nfm21]
C194  0.1uF  [0201]
C195  0.1uF  [0201]
C196  0.1uF  [0201]
C197  0.1uF  [0201]
C198  1500pF  [0201]
C199  1500pF  [0201]
C200  1500pF  [0201]
C201  1500pF  [0201]
C202  1500pF  [0201]
C203  1500pF  [0201]
C204  1500pF  [0201]
C205  1500pF  [0201]
C206  1500pF  [0201]
C207  1500pF  [0201]
C208  1500pF  [0201]
C210  2.2uF  [0402]
C211  2.2uF  [0402]
C212  3000pF  [0402]
C213  0.1uF  [0201]
C214  0.1uF  [0201]
C215  0.1uF  [0201]
C216  0.1uF  [0201]
C217  0.1uF  [0201]
C218  22uF  [0805]
C219  22uF  [0805]
C220  22uF  [0805]
C221  22uF  [0805]
C226  0.1uF  [0201]
C227  0.1uF  [0201]
C228  0.1uF  [0201]
C229  0.1uF  [0201]
C230  0.1uF  [0201]
C231  0.1uF  [0201]
C232  0.1uF  [0201]
C233  1500pF  [0201]
C234  1500pF  [0201]
C237  2.2uF  [0402]
C238  2.2uF  [0402]
C239  3000pF  [0402]
C240  0.1uF  [0201]
C241  0.1uF  [0201]
C242  0.1uF  [0201]
C243  0.1uF  [0201]
C244  0.1uF  [0201]
C1065  22uF  [0805]
C1066  22uF  [0805]
C1138  3000pF  [0402]
FB5  BLM18PG121SN1  [0603]
FB6  BLM18PG121SN1  [0603]
FB7  BLM18PG121SN1  [0603]
J6  JMP2  [jmp_p254_t_1x2]
J7  JMP2  [jmp_p254_t_1x2]
J8  JMP2  [jmp_p254_t_1x2]
R171  330  [0402]
R172  330  [0402]
R173  330  [0402]
TP15  TP  [tp]
TP16  TP  [tp]
TP17  TP  [tp]
TP18  TP  [tp]
sheet 13 Proc Gnd
C245  470uF  [7343]
C246  470uF  [7343]
C247  47uF  [0805]
C248  47uF  [0805]
C249  0.1uF  [0402]
C250  0.1uF  [0402]
C251  0.1uF  [0402]
C252  0.1uF  [0402]
C253  0.1uF  [0402]
C254  0.1uF  [0402]
C255  0.1uF  [0402]
C256  0.1uF  [0402]
C257  0.1uF  [0402]
C258  0.1uF  [0402]
C259  0.1uF  [0402]
C260  0.1uF  [0402]
C261  10uF  [0603]
C262  1uF  [0402]
C263  3000pF  [0402]
C264  4.7uF  [0603]
C265  47uF  [0805]
C266  10uF  [0603]
C267  1uF  [0402]
C268  3000pF  [0402]
C269  4.7uF  [0603]
C270  47uF  [0805]
C271  10uF  [0603]
C272  1uF  [0402]
C273  10uF  [0603]
C274  1uF  [0402]
R174  5.1  [0402]
R175  0.33  [0402]
R176  0  [0402]
R177  5.1  [0402]
R178  0.33  [0402]
R179  0  [0402]
R180  5.1  [0402]
R181  5.1  [0402]
sheet 14 UART&I2C
C275  0.1uF  [0402]
C276  0.1uF  [0402]
C277  0.1uF  [0402]
C278  0.1uF  [0402]
C279  0.1uF  [0402]
C280  100pF  [0402]
C281  100pF  [0402]
C282  100pF  [0402]
C283  100pF  [0402]
C284  0.1uF  [0402]
C285  0.1uF  [0402]
C286  0.1uF  [0402]
C287  0.1uF  [0402]
C288  0.1uF  [0402]
C289  100pF  [0402]
C290  100pF  [0402]
C291  100pF  [0402]
C292  100pF  [0402]
C293  0.1uF  [0402]
C294  10uF  [0603]
C295  0.1uF  [0402]
C296  1000pF  [0402]
C297  0.1uF  [0402]
FB8  BLM18BD601SN1  [0603]
FB9  BLM18BD601SN1  [0603]
FB10  BLM18BD601SN1  [0603]
FB11  BLM18BD601SN1  [0603]
FB12  BLM18BD601SN1  [0603]
FB13  BLM18BD601SN1  [0603]
FB14  BLM18BD601SN1  [0603]
FB15  BLM18BD601SN1  [0603]
J9  2XDB9  [DUALDB-9MM]  (sections A,B)
J10  BAT_SOCKET  [con_bat_wba3b2]
R182  100  [0402]
R183  100  [0402]
R184  100  [0402]
R185  100  [0402]
R186  100  [0402]
R187  100  [0402]
R188  100  [0402]
R189  100  [0402]
R190  4.7K  [0402]
R191  1K  [0402]
R192  4.7K  [0402]
R193  100  [0402]
R194  100  [0402]
R195  4.7K  [0402]
U29  MAX3232  [tssop_16]
U30  MAX3232  [tssop_16]
U31  DS1339U-33+  [msop_8]
U32  AT24C256  [so_8]
U33  LCDA15C-8  [so_16]
U34  ADT7461  [msop_8]
Y1  32.768KHz  [cry_69x14_4]
sheet 15 TDM
C298  10uF  [1206]
C299  0.1uF  [0603]
C300  10uF  [0603]
C301  0.1uF  [0402]
C302  0.1uF  [0402]
C303  0.1uF  [0402]
J11  CONN_2X20  [con_mec6_120]
R196  4.7K  [0402]
R197  4.7K  [0402]
R198  4.7K  [0402]
R199  4.7K  [0402]
R200  51  [0402]
R201  33  [0402]
R202  51  [0402]
sheet 16 HDMI
C304  0.1uF  [0402]
C305  0.1uF  [0402]
C306  0.1uF  [0402]
C307  0.1uF  [0402]
C308  0.1uF  [0402]
C309  0.1uF  [0402]
C310  0.1uF  [0402]
C311  0.1uF  [0402]
C312  0.1uF  [0402]
C313  0.1uF  [0402]
C314  0.1uF  [0402]
C315  0.1uF  [0402]
C316  0.1uF  [0402]
D4  GRN  [led_0603]
FB16  BLM18PG121SN1  [0603]
FB17  BLM18PG121SN1  [0603]
FB46  BLM18PG121SN1  [0603]
J12  HDMI_A  [con_hdmi]
L19  90ohm  [ind_cm_2012]
L20  90ohm  [ind_cm_2012]
L21  90ohm  [ind_cm_2012]
L22  90ohm  [ind_cm_2012]
R203  4.7K  [0402]
R204  4.7K  [0402]
R205  49.9K  [0402]
R206  49.9K  [0402]
R207  49.9K  [0402]
R208  49.9K  [0402]
R209  49.9K  [0402]
R210  0  [0402]
R211  49.9K  [0402]
R212  140  [0402]
R213  2.37K  [0402]
R214  1K  [0402]
R215  15K  [0402]
R216  4.7K  [0402]
R217  4.7K  [0402]
R218  1K  [0402]
R219  0  [0402]
R220  330  [0402]
R768  0  [0402]
R769  0  [0402]
R770  0  [0402]
R771  0  [0402]
R772  0  [0402]
R773  0  [0402]
R774  0  [0402]
R775  0  [0402]
U35  CH7301C  [qfp_p050_64]
U36  CM2020  [tssop_38]
sheet 17 LCD
C317  10uF  [0603]
C318  0.1uF  [0402]
C319  0.1uF  [0402]
C320  0.1uF  [0402]
C321  0.1uF  [0402]
C322  10uF  [1206]
C323  0.1uF  [0603]
C324  0.1uF  [0603]
C325  0.1uF  [0402]
C326  0.1uF  [0402]
C327  0.1uF  [0402]
C328  0.1uF  [0402]
C329  0.1uF  [0402]
C330  0.1uF  [0402]
C331  0.1uF  [0402]
F1  1A  [1206]
FB18  BLM18PG121SN1  [0603]
J13  DF14-20P-1.25H  [con_fpc_df14_20p]
J14  HDR_1X2  [jmp_p254_t_1x2]
J15  HDR_1X2  [jmp_p254_t_1x2]
J16  CON_3PIN  [con_wafer_p254_s_1x3]
J17  CON_3PIN  [con_wafer_p254_s_1x3]
M1  LQ150X1LW71N  [none]
Q6  IRLML6346  [sot23]
R221  4.7K  [0402]
R222  4.7K  [0402]
R223  49.9K  [0402]
R224  4.7K  [0402]
R225  49.9K  [0402]
R226  0  [0402]
R227  4.7K  [0402]
R228  49.9K  [0402]
R229  4.7K  [0402]
R230  4.7K  [0402]
R231  4.7K  [0402]
R232  4.7K  [0402]
R233  0  [1206]
R234  4.7K  [0402]
R235  4.7K  [0402]
U37  DS90C387R  [qfp_p050_100]
sheet 18 Profibus
C332  10uF  [1206]
C333  10uF  [1206]
C334  0.1uF  [0402]
C336  0.1uF  [0402]
C337  0.1uF  [0402]
C338  0.1uF  [0402]
J18  JMP2  [jmp_p254_t_1x2]
J42  HDR_1X5  [hdr_p254_m_t_1x5]
L3  10uH  [0806]
R236  0  [1206]
R237  270K  [0603]
R238  0  [1206]
R239  4.7K  [0402]
R240  4.7K  [0402]
R241  4.7K  [0402]
R242  0  [1206]
R243  100  [1206]
R244  0  [1206]
R245  4.7K  [0402]
R246  4.7K  [0402]
U38  NKE0505SC  [sip4_2p54_11x6]
U39  74CBTLV3257  [tssop_16]
U40  ISO1176DW  [soic16_1p27_7p6x10p5]
U41  74LVC1G14  [sc70_5]
sheet 19 EC1 PHY
C339  0.01uF  [0402]
C341  0.01uF  [0402]
C342  0.01uF  [0402]
C343  10pF  [0402]
C344  0.01uF  [0402]
C345  1000pF  [1206]
C346  10pF  [0402]
C347  1000pF  [1206]
C348  470pF  [0402]
C349  470pF  [0402]
C350  4.7pF  [0402]
C351  4.7pF  [0402]
C352  1000pF  [0402]
C353  1000pF  [1206]
C354  4.7uF  [0603]
C355  0.1uF  [0402]
C356  0.1uF  [0402]
C357  0.1uF  [0402]
C358  0.1uF  [0402]
C359  0.1uF  [0402]
C360  0.1uF  [0402]
C361  0.1uF  [0402]
C362  0.1uF  [0402]
C363  0.1uF  [0402]
C364  0.1uF  [0402]
C365  4.7uF  [0603]
C366  0.1uF  [0402]
C367  0.1uF  [0402]
L4  2.2uH  [ind_swpa2520]
R247  75  [0603]
R248  75  [0603]
R249  75  [0603]
R250  33  [0402]
R251  33  [0402]
R252  75  [0603]
R253  33  [0402]
R254  33  [0402]
R255  33  [0402]
R256  33  [0402]
R258  33  [0402]
R259  510  [0402]
R260  510  [0402]
R262  0  [0402]
R263  0  [0402]
R264  0  [0402]
R265  4.7K  [0402]
R266  15  [0402]
R267  0  [0402]
R268  2.49K  [0402]
R269  4.7K  [0402]
R270  4.7K  [0402]
R271  4.7K  [0402]
R272  4.7K  [0402]
R273  4.7K  [0402]
R274  4.7K  [0402]
R275  4.7K  [0402]
R276  4.7K  [0402]
T1  H5008  [mag_h5008]
U42  RTL8211E-VB  [qfn_p040_d040_b600_48_e440]
Y2  25MHz  [cry_32x25_4]
sheet 20 EC2 PHY
J19  RJ45_LED_2X1  [con_rj45_2x1_led]  (sections A,B)

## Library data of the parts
U1 = T1040: TYPE: IC; Vendor: Freescale
C79-C86 C249-C260 C275-C279 C284-C288 C293 C295 C297 C301-C316 C318-C321 C325-C331 C334 C336-C338 C355-C364 C366 C367 = CAP: VOLTAGE: 16V
R170-R174 R176 R177 R179-R209 R211 R214-R218 R220-R225 R227 R229 R230 R233-R241 R243 R245 R247-R256 R258-R260 R262-R265 R267 R269-R276 = RES: TOL: 5%
U21-U24 U26-U28 = 74CBTLV3253: MPN: SN74CBTLV3253PWR; TYPE: IC; Vendor: TI
U25 = 74LVC125: MPN: SN74LVC125APWR; TYPE: IC; Vendor: TI
C87-C96 C99-C106 C109-C117 C119-C121 C125-C156 C161-C191 C194-C197 C213-C221 C226-C232 C240-C244 C247 C248 C261 C262 C264-C267 C269-C274 C294 C300 C317 C354 C365 C1065 C1066 = CAP: VOLTAGE: 6.3V
C97 C98 C108 C118 C123 C124 C210 C211 C237 C238 = CAP: VOLTAGE: 4V
C107 C122 C212 C239 C263 C268 C280-C283 C289-C292 C296 C348-C351 C1138 = CAP: VOLTAGE: 50V
C192 C193 = CAP_3T_4P: TYPE: CAP; Vendor: Murata
C198-C208 C233 C234 C298 C299 C322-C324 C332 C333 C339 C341 C342 C344 = CAP: VOLTAGE: 25V
FB5-FB18 FB46 = BEAD: Vendor: Murata
J6-J8 = JMP2: MPN: TSW-102-07-F-S; TYPE: CON; Vendor: Samtec
TP15-TP18 = TP: TYPE: PAD
C245 C246 = CAP_E: MPN: 2R5TPE470M7; TYPE: CAP; VOLTAGE: 2.5V; Vendor: SANYO
R175 R178 R212 R213 R268 = RES: TOL: 1%
J9 = DSD9M: CON 9 DB 0.318 DUAL PLUG/PLUG RA SHLD TH 54.5MIL SP 1250H AU 125L; AGILE_PN: 210-76422; CAD_APPROVED: Yes; HEIGHT: 31.75MM; LABEL: TOP; MFG_NAME01: NORCOMP; MFG_PN01: 178-009-613R571; MPN: 178-009-613R571; ROHS: Yes; TYPE: CON; Vendor: NORCOMP
J10 = BAT_SOCKET: MPN: WBA3B2 U; TYPE: CON; Vendor: WIN WIN PRECISION INDUSTRIAL
U29 U30 = MAX3232: MPN: MAX3232IPW; TYPE: IC; Vendor: TI
U31 = DS1339U: TYPE: IC; Vendor: Maxim
U32 = EEPROM-I2C: MPN: AT24C256C-SSHL-B; TYPE: IC; Vendor: Atmel
U33 = LCDA15C-8: BOM_IGNORE: DNP; MPN: LCDA15C-8.TBT; TYPE: IC; Vendor: Semtech
U34 = ADT7461: MPN: ADT7461ARMZ-R7; TYPE: IC; Vendor: ON Semi
Y1 = CRYSTAL_32K: MPN: 6.9x1.4mm,4pin,+/-20ppm; TYPE: XTAL
J11 = CONN_2X20: MPN: MEC6-120-02-S-DV-A-K-TR; TYPE: CON; Vendor: Samtec
D4 = LED: MPN: 0603,Green
J12 = HDMI_CONN: MPN: 3690019-014-R; TYPE: CON; Vendor: Astron
L19-L22 = IND_CM: MPN: DLW21HN900SQ2L; TYPE: IND; Vendor: Murata
R210 R219 R226 R228 R231 R232 R242 R244 R246 R266 R768-R775 = RES: BOM_IGNORE: DNP; TOL: 5%
U35 = CH7301C: MPN: CH7301C-TF-TR; TYPE: IC; Vendor: Chrontel
U36 = CM2020: MPN: CM2020-01TR; TYPE: IC; Vendor: ON Semi
F1 = PTC: BOM_IGNORE: DNP; MPN: 1206L100; Vendor: Littelfuse
J13 = FPC_20PIN: TYPE: CON; Vendor: HRS
J14 J15 J18 = CONN_1X2: MPN: TSW-102-07-F-S; TYPE: HDR; Vendor: Samtec
J16 J17 = CONN_3PIN: MPN: WRFB-DS03T2NNAX-X; TYPE: CON; Vendor: SUPERIOR TECH
M1 = LCD: TYPE: MDL
Q6 = NMOS: MPN: IRLML6346TRPBF; TYPE: MOS; Vendor: IR
U37 = DS90C387R: MPN: DS90C387RVJD/NOPB; TYPE: IC; Vendor: TI
J42 = CONN_1X5: MPN: TSW-105-07-F-S; TYPE: HDR; Vendor: Samtec
L3 = IND: MPN: LBC2016T100M; Vendor: TAIYO YUDEN
U38 = NKE0505SC_SIP_4P: IC LIN DCDC ISOLATED 1W 5V SIP4; AGILE_PN: 315-79395; CAD_APPROVED: Yes; HEIGHT: 7.7MM; MFG_NAME01: Murata Power Solutions Inc; ROHS: Yes; TYPE: IC; Vendor: Murata
U39 = 74CBTLV3257: MPN: SN74CBTLV3257PWR; TYPE: IC; Vendor: TI
U40 = ISO1176_SO16: IC XCVR RS485 PROFIBUS 3.15-5.5V SOIC16; AGILE_PN: 312-80327; CAD_APPROVED: Yes; HEIGHT: 2.65MM; MFG_NAME01: Texas Instruments; ROHS: Yes; TYPE: IC; Vendor: TI
U41 = 74LVC1G14: MPN: SN74LVC1G14DCKR; TYPE: IC; Vendor: TI
C343 C346 C352 = CAP: BOM_IGNORE: DNP; VOLTAGE: 50V
C345 C347 C353 = CAP: VOLTAGE: 2KV
L4 = IND_IRON: MPN: SWPA252012S2R2MT; TYPE: IND; Vendor: Sunlord
T1 = H5007: TYPE: XFMR; Vendor: Pulse
U42 = RTL8211E-VB: MPN: RTL8211E-VB-CG; TYPE: IC; Vendor: Realtek
Y2 = CRYSTAL_4PIN_v2: MPN: 3.2x2.5mm,+/-20ppm; TYPE: XTAL
J19 = RJ45_LED_2X1: MPN: 10118075-510B010LF; TYPE: CON; Vendor: FCI

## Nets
1V0_FA_VL: C174.1 J8.1 R173.2 U1.G18(FA_VL)
1V0_USB_SVDD: C95.1 C96.1 C97.1 C98.1 C1138.1 FB5.1 U1.K9(USB_SVDD1) U1.K10(USB_SVDD2)
1V0S: C192.2 ; also on sheet 34
1V2: C87.1 C88.1 C89.1 C90.1 C91.1 C92.1 C93.1 C94.1 C99.1 C100.1 C101.1 C102.1 C103.1 C104.1 C109.1 C110.1 C111.1 C112.1 C113.1 C114.1 C115.1 C116.1 C117.1 C119.1 C1065.1 C1066.1 U1.AA27(G1VDD17) U1.AD27(G1VDD18) U1.AF27(G1VDD19) U1.D27(G1VDD01) U1.F27(G1VDD02) U1.H27(G1VDD03) U1.K21(G1VDD04) U1.K27(G1VDD05) U1.L21(G1VDD06) U1.M21(G1VDD07) U1.M27(G1VDD08) U1.N21(G1VDD09) U1.P21(G1VDD10) U1.P27(G1VDD11) U1.R21(G1VDD12) U1.T21(G1VDD13) U1.U21(G1VDD14) U1.U27(G1VDD15) U1.W27(G1VDD16) ; also on sheet 3 35
1V2_SLP: C245.1 C246.1 C247.1 C248.1 C249.1 C250.1 C251.1 C252.1 C253.1 C254.1 C255.1 C256.1 C257.1 C258.1 C259.1 C260.1 ; also on sheet 3 33 34 35
1V05_EC1_AVDD: C354.1 C355.1 C362.1 C363.1 C364.1 L4.2 R267.2 U42.3(AVDD10) U42.9(AVDD10) U42.40(AVDD10)
1V05_EC1_DVDD: C358.1 C359.1 R267.1 U42.28(DVDD10) U42.36(DVDD10)
1V8: C146.1 C147.1 C148.1 C149.1 C150.1 C151.1 C152.1 C183.1 R174.1 R177.1 R181.1 U1.G9(TH_VDD) U1.J14(OVDD1) U1.J15(OVDD2) U1.J16(OVDD3) U1.J17(OVDD4) U1.J18(OVDD5) U1.J19(OVDD6) ; also on sheet 4 5 7 29 30 35
1V8_MTR: C161.1 J7.1 R172.2 U1.F11(PROG_MTR)
1V8_SFP: C144.1 J6.1 R171.2 U1.F12(PROG_SFP)
1V8_SLP: C162.1 C163.1 C164.1 C170.1 FB7.2 J6.2 J7.2 R180.1 U1.J11(O1VDD1) U1.J12(O1VDD2) U1.J13(O1VDD3) ; also on sheet 7 29 30 31 33 34 35
1V8_USB_OVDD: C120.1 C121.1 C122.1 C123.1 C124.1 FB7.1 U1.J9(USB_OVDD1) U1.J10(USB_OVDD2)
1V35X: C193.1 R175.2 R178.2 ; also on sheet 34
2V5: C125.1 C126.1 C127.1 U1.V8(LVDD1) U1.W8(LVDD2) ; also on sheet 8 20 21 22 23 24 25 26 35
2V5_SLP: C128.1 C129.1 C130.1 C356.1 C357.1 R270.2 R271.2 R272.2 R273.2 U1.T8(L1VDD1) U1.U8(L1VDD2) U42.15(DVDD33) U42.21(DVDD33) ; also on sheet 7 8 33 35
3V3: C79.1 C80.1 C81.1 C82.1 C83.1 C84.1 C85.1 C86.1 C131.1 C132.1 C133.1 C134.1 C135.1 C276.1 C285.1 C293.1 C300.1 C301.1 C302.1 C303.1 C307.1 C309.1 C310.1 C311.1 C312.1 C313.1 C314.1 C317.1 C318.1 C319.1 C325.1 C326.1 C327.1 C328.1 C329.1 C330.1 C331.1 C336.1 C337.1 C338.1 FB16.1 FB17.1 FB18.1 J11.10 J11.12 J11.14 J11.16 J13.1 J13.2 R196.1 R197.1 R198.1 R199.1 R205.2 R206.2 R207.2 R208.2 R214.1 R216.1 R217.1 R221.2 R222.2 R224.1 R226.1 R227.2 R228.1 R229.1 R230.1 R231.1 R232.1 R241.2 R246.2 U1.M8(CVDD1) U1.N8(DVDD1) U1.P8(DVDD2) U1.R8(DVDD3) U21.16(VCC) U22.16(VCC) U23.16(VCC) U24.16(VCC) U25.14(VCC) U26.16(VCC) U27.16(VCC) U28.16(VCC) U29.16(VCC) U30.16(VCC) U32.8(VCC) U35.1(DVDD) U35.12(DVDD) U35.23(TVDD) U35.29(TVDD) U35.45(DVDDV) U35.49(DVDD) U36.2(LV_SUPPLY) U37.13(PLLSEL) U37.30(LVDSVCC) U37.40(LVDSVCC) U37.48(LVDSVCC) U37.53(VCC) U37.61(I2CSEL) U37.68(I2CVCC) U37.70(VCC3V) U37.72(TST1) U37.78(VREF) U37.79(VCC3V) U37.95(VCC3V) U39.16(VCC) U40.1(VCC1) U41.5(VCC) ; also on sheet 5 6 7 9 20 21 22 23 27 30 35
3V3_DFP_PLLVCC: C320.1 C321.1 FB18.2 U37.10(PLLVCC) U37.16(PLLVCC)
3V3_DVI_AVDD: C316.1 FB17.2 U35.18(AVDD)
3V3_DVI_VDD: C315.1 FB16.2 U35.33(VDD)
3V3_SLP: C295.1 C297.1 C360.1 C361.1 C365.1 C366.1 C367.1 FB6.2 R190.2 R192.2 R195.2 R263.1 R265.1 R276.2 U31.8(VCC) U34.1(VDD) U42.6(AVDD33) U42.37(DVDD33) U42.41(AVDD33) U42.44(VDDREG) U42.45(VDDREG) ; also on sheet 3 7 10 28 29 30 32 33 34 35 36
3V3_USB_HVDD: C105.1 C106.1 C107.1 C108.1 C118.1 FB6.1 U1.J8(USB_HVDD1) U1.K8(USB_HVDD2)
5V0: C308.1 C332.1 R236.1 U36.1(5V_SUPPLY) U38.2(+VIN) ; also on sheet 35
5V0_HDMI: C305.1 FB46.2 J12.18(+5V) R203.2 R204.2
12V: C298.1 C299.1 C322.1 C323.1 C324.1 F1.1 J11.2 J11.4 J11.6 R233.1 ; also on sheet 27 35 36
AGND_SD1_PLL1: C263.2 C264.2 C265.2 R176.1 U1.AA16(AGND_SD1_PLL1)
AGND_SD1_PLL2: C268.2 C269.2 C270.2 R179.1 U1.AA20(AGND_SD1_PLL2)
AVDD_CGA1: C261.1 C262.1 R174.2 U1.G11(AVDD_CGA1)
AVDD_CGA2: C266.1 C267.1 R177.2 U1.G12(AVDD_CGA2)
AVDD_DDR1: C273.1 C274.1 R181.2 U1.E20(AVDD_D1)
AVDD_PLAT: C271.1 C272.1 R180.2 U1.G10(AVDD_PLAT)
AVDD_SD1_PLL1: C263.1 C264.1 C265.1 R175.1 U1.AB16(AVDD_SD1_PLL1)
AVDD_SD1_PLL2: C268.1 C269.1 C270.1 R178.1 U1.AB20(AVDD_SD1_PLL2)
GND: C79.2 C80.2 C81.2 C82.2 C83.2 C84.2 C85.2 C86.2 C87.2 C88.2 C89.2 C90.2 C91.2 C92.2 C93.2 C94.2 C95.2 C96.2 C97.2 C98.2 C99.2 C100.2 C101.2 C102.2 C103.2 C104.2 C105.2 C106.2 C107.2 C108.2 C109.2 C110.2 C111.2 C112.2 C113.2 C114.2 C115.2 C116.2 C117.2 C118.2 C119.2 C120.2 C121.2 C122.2 C123.2 C124.2 C125.2 C126.2 C127.2 C128.2 C129.2 C130.2 C131.2 C132.2 C133.2 C134.2 C135.2 C136.2 C137.2 C138.2 C139.2 C140.2 C141.2 C142.2 C143.2 C144.2 C145.2 C146.2 C147.2 C148.2 C149.2 C150.2 C151.2 C152.2 C153.2 C154.2 C155.2 C156.2 C161.2 C162.2 C163.2 C164.2 C165.2 C166.2 C167.2 C168.2 C169.2 C170.2 C171.2 C172.2 C173.2 C174.2 C175.2 C176.2 C177.2 C178.2 C179.2 C180.2 C181.2 C182.2 C183.2 C184.2 C185.2 C186.2 C187.2 C188.2 C189.2 C190.2 C191.2 C192.3 C192.4 C193.3 C193.4 C194.2 C195.2 C196.2 C197.2 C198.2 C199.2 C200.2 C201.2 C202.2 C203.2 C204.2 C205.2 C206.2 C207.2 C208.2 C210.2 C211.2 C212.2 C213.2 C214.2 C215.2 C216.2 C217.2 C218.2 C219.2 C220.2 C221.2 C226.2 C227.2 C228.2 C229.2 C230.2 C231.2 C232.2 C233.2 C234.2 C237.2 C238.2 C239.2 C240.2 C241.2 C242.2 C243.2 C244.2 C245.2 C246.2 C247.2 C248.2 C249.2 C250.2 C251.2 C252.2 C253.2 C254.2 C255.2 C256.2 C257.2 C258.2 C259.2 C260.2 C261.2 C262.2 C266.2 C267.2 C271.2 C272.2 C273.2 C274.2 C276.2 C277.2 C279.2 C280.2 C281.2 C282.2 C283.2 C285.2 C287.2 C288.2 C289.2 C290.2 C291.2 C292.2 C293.2 C294.2 C295.2 C297.2 C298.2 C299.2 C300.2 C301.2 C302.2 C303.2 C304.2 C305.2 C306.1 C307.2 C308.2 C309.2 C310.2 C311.2 C312.2 C313.2 C314.2 C315.2 C316.2 C317.2 C318.2 C319.2 C320.2 C321.2 C322.2 C323.2 C324.2 C325.2 C326.2 C327.2 C328.2 C329.2 C330.2 C331.2 C332.2 C336.2 C337.2 C338.2 C339.1 C341.1 C342.1 C343.1 C344.1 C346.2 C347.1 C348.2 C349.2 C350.2 C351.2 C352.2 C353.1 C354.2 C355.2 C356.2 C357.2 C358.2 C359.2 C360.2 C361.2 C362.2 C363.2 C364.2 C365.2 C366.2 C367.2 C1065.2 C1066.2 C1138.2 D4.1 J9.5 J9.15 J10.2 J11.5 J11.15 J11.19 J11.23 J11.26 J11.30 J11.37 J11.40 J12.2(D2_Shield) J12.5(D1_Shield) J12.8(D0_Shield) J12.11(CK_Shield) J12.17(GND) J13.3 J13.4 J13.7 J13.10 J13.13 J13.16 J13.21 J13.22 J14.2 J16.1 J16.3 J17.2 J19.B10 J19.B12 Q6.2(S) R171.1 R172.1 R173.1 R176.2 R179.2 R209.1 R211.1 R212.2 R213.2 R215.1 R218.1 R219.1 R223.1 R225.1 R234.1 R235.1 R238.1 R239.1 R240.1 R245.1 R268.1 R269.2 R274.2 R275.2 U1.A2(GND001) U1.A20(GND002) U1.A27(GND003) U1.AA11(GND148) U1.AA13(S1GND05) U1.AA15(S1GND06) U1.AA17(S1GND07) U1.AA19(S1GND08) U1.AA21(S1GND09) U1.AA24(GND149) U1.AB2(GND150) U1.AB5(GND151) U1.AB7(GND152) U1.AB13(S1GND10) U1.AB17(S1GND11) U1.AB21(S1GND12) U1.AB22(GND153) U1.AB26(GND154) U1.AC10(X1GND01) U1.AC11(X1GND02) U1.AC13(X1GND03) U1.AC14(X1GND04) U1.AC16(X1GND05) U1.AC17(X1GND06) U1.AC19(X1GND07) U1.AC20(X1GND08) U1.AC24(GND155) U1.AC26(GND156) U1.AD4(GND157) U1.AD6(GND158) U1.AD9(X1GND09) U1.AD12(X1GND10) U1.AD15(X1GND11) U1.AD18(X1GND12) U1.AD21(X1GND13) U1.AD22(GND159) U1.AE2(GND160) U1.AE9(X1GND14) U1.AE12(X1GND15) U1.AE15(X1GND16) U1.AE18(X1GND17) U1.AE21(X1GND18) U1.AE24(GND161) U1.AE26(GND162) U1.AF9(GND163) U1.AF10(S1GND13) U1.AF11(S1GND14) U1.AF12(S1GND15) U1.AF13(S1GND16) U1.AF14(S1GND17) U1.AF15(S1GND18) U1.AF16(S1GND19) U1.AF17(S1GND20) U1.AF18(S1GND21) U1.AF19(S1GND22) U1.AF20(S1GND23) U1.AF21(GND164) U1.AG1(GND165) U1.AG4(GND166) U1.AG6(GND167) U1.AG9(S1GND24) U1.AG12(S1GND25) U1.AG15(S1GND26) U1.AG18(S1GND27) U1.AG21(S1GND28) U1.AG22(GND168) U1.AG23(GND169) U1.AG26(GND170) U1.AH2(GND171) U1.AH9(S1GND29) U1.AH12(S1GND30) U1.AH15(S1GND31) U1.AH18(S1GND32) U1.AH21(S1GND33) U1.B1(GND004) U1.B4(GND005) U1.B7(GND006) U1.B10(GND007) U1.B13(GND008) U1.B16(GND009) U1.B19(GND010) U1.B23(GND011) U1.B25(GND012) U1.B28(GND013) U1.C22(GND014) U1.C26(GND015) U1.D2(GND016) U1.D20(GND017) U1.D21(GND018) U1.D24(GND019) U1.E1(USB_AGND01) U1.E2(USB_AGND02) U1.E3(USB_AGND03) U1.E5(GND020) U1.E7(GND021) U1.E10(GND022) U1.E13(GND023) U1.E16(GND024) U1.E19(GND025) U1.E22(GND026) U1.E26(GND027) U1.F3(USB_AGND04) U1.F15(GND028) U1.F24(GND029) U1.G1(USB_AGND05) U1.G2(USB_AGND06) U1.G3(USB_AGND07) U1.G5(USB_AGND08) U1.G7(GND030) U1.G13(GND031) U1.G16(GND032) U1.G22(GND033) U1.G26(GND034) U1.H3(USB_AGND09) U1.H7(GND035) U1.H8(GND036) U1.H9(GND037) U1.H10(GND038) U1.H11(GND039) U1.H12(GND040) U1.H13(GND041) U1.H14(GND042) U1.H15(GND043) U1.H16(GND044) U1.H17(GND045) U1.H18(GND046) U1.H19(GND047) U1.H20(GND048) U1.H24(GND049) U1.J1(USB_AGND10) U1.J2(USB_AGND11) U1.J3(USB_AGND12) U1.J7(GND050) U1.J22(GND051) U1.J26(GND052) U1.K2(GND053) U1.K5(GND054) U1.K6(GND055) U1.K7(GND056) U1.K12(GND057) U1.K14(GND058) U1.K16(GND059) U1.K18(GND060) U1.K20(GND061) U1.K24(GND062) U1.L7(GND063) U1.L9(GND064) U1.L11(GND065) U1.L13(GND066) U1.L15(GND067) U1.L17(GND068) U1.L19(GND069) U1.L22(GND070) U1.L26(GND071) U1.M7(GND072) U1.M10(GND073) U1.M12(GND074) U1.M14(GND075) U1.M16(GND076) U1.M18(GND077) U1.M20(GND078) U1.M24(GND079) U1.N2(GND080) U1.N5(GND081) U1.N7(GND082) U1.N9(GND083) U1.N11(GND084) U1.N13(GND085) U1.N15(GND086) U1.N17(GND087) U1.N19(GND088) U1.N22(GND089) U1.N26(GND090) U1.P7(GND091) U1.P10(GND092) U1.P12(GND093) U1.P14(GND094) U1.P16(GND095) U1.P18(GND096) U1.P20(GND097) U1.P24(GND098) U1.R7(GND099) U1.R9(GND100) U1.R11(GND101) U1.R13(GND102) U1.R15(GND103) U1.R17(GND104) U1.R19(GND105) U1.R22(GND106) U1.R26(GND107) U1.T2(GND108) U1.T5(GND109) U1.T7(GND110) U1.T10(GND111) U1.T12(GND112) U1.T14(GND113) U1.T16(GND114) U1.T18(GND115) U1.T20(GND116) U1.T22(GND117) U1.T26(GND118) U1.U7(GND119) U1.U9(GND120) U1.U11(GND121) U1.U13(GND122) U1.U15(GND123) U1.U17(GND124) U1.U19(GND125) U1.U24(GND126) U1.V7(GND127) U1.V10(GND128) U1.V12(GND129) U1.V14(GND130) U1.V16(GND131) U1.V18(GND132) U1.V20(GND133) U1.V22(GND134) U1.V26(GND135) U1.W2(GND136) U1.W5(GND137) U1.W7(GND138) U1.W9(GND139) U1.W11(GND140) U1.W13(GND141) U1.W24(GND142) U1.Y7(GND143) U1.Y10(GND144) U1.Y12(GND145) U1.Y14(S1GND01) U1.Y16(S1GND02) U1.Y17(S1GND03) U1.Y18(S1GND04) U1.Y22(GND146) U1.Y26(GND147) U21.1(1~{OE}) U21.8(GND) U21.15(2~{OE}) U22.1(1~{OE}) U22.8(GND) U22.15(2~{OE}) U23.1(1~{OE}) U23.8(GND) U23.15(2~{OE}) U24.1(1~{OE}) U24.8(GND) U24.15(2~{OE}) U25.1(~{1OE}) U25.4(~{2OE}) U25.7(GND) U25.10(~{3OE}) U25.13(~{4OE}) U26.1(1~{OE}) U26.8(GND) U26.15(2~{OE}) U27.1(1~{OE}) U27.8(GND) U27.15(2~{OE}) U28.1(1~{OE}) U28.8(GND) U28.15(2~{OE}) U29.15(GND) U30.15(GND) U31.4(GND) U32.1(A0) U32.2(A1) U32.3(A2) U32.4(GND) U32.7(WP) U33.9 U33.10 U33.11 U33.12 U33.13 U33.14 U33.15 U33.16 U34.5(GND) U35.6(DGND) U35.11(DGND) U35.17(AGND) U35.20(TGND) U35.26(TGND) U35.32(TGND) U35.34(GND) U35.36(TEST) U35.40(GND) U35.64(DGND) U36.3(GND) U36.5(TMDS_GND) U36.8(TMDS_GND) U36.11(TMDS_GND) U36.14(TMDS_GND) U36.25(TMDS_GND) U36.28(TMDS_GND) U36.31(TMDS_GND) U36.34(TMDS_GND) U36.36(GND) U37.1(D19) U37.2(D18) U37.3(D17) U37.4(D16) U37.5(D15) U37.6(D14) U37.7(D13) U37.8(D12) U37.9(GND) U37.11(GND) U37.14(PLLGND) U37.15(PLLGND) U37.17(PLLGND) U37.20(RSVD1) U37.25(LVDSGND) U37.35(LVDSGND) U37.43(LVDSGND) U37.51(LVDSGND) U37.52(GND) U37.54(RSVD2) U37.56(RSVD4) U37.57(RSVD5) U37.58(RSVD6) U37.62(RSVD7) U37.63(A0) U37.64(A1) U37.65(A2) U37.66(RSVD8) U37.67(RSVD9) U37.69(SGND) U37.71(GND3V) U37.77(GND) U37.80(GND3V) U37.96(GND3V) U37.97(D23) U37.98(D22) U37.99(D21) U37.100(D20) U38.1(-VIN) U39.8(GND) U39.15(~{OE}) U40.2(GND1_1) U40.8(GND1_2) U41.3(GND) U42.47(GND) U42.49(EPAD) Y1.2 Y1.3 Y2.2 Y2.4 ; also on sheet 3 4 5 6 7 8 9 10 20 21 22 23 24 25 26 27 28 29 30 31 32 33 34 35 36 37
GND_PROFI: C333.2 C334.2 J42.5 R237.1 R238.2 R244.1 U38.3(-VOUT) U40.9(GND2_1) U40.15(GND2_2)
SVDD: C192.1 C210.1 C211.1 C212.1 C213.1 C214.1 C215.1 C216.1 C217.1 U1.W15(S1VDD1) U1.W16(S1VDD2) U1.W17(S1VDD3) U1.W18(S1VDD4) U1.W19(S1VDD5) U1.W20(S1VDD6) U1.Y13(S1VDD7) ; also on sheet 8
VCC_PROFI: C333.1 C334.1 J42.1 L3.2 R237.2 R242.2 U40.16(VCC2)
VDD_LP: U1.P6(VDD_LP)
CK_N: J12.12(CK-) L22.2 R775.2
CK_P: J12.10(CK+) L22.3 R774.2
D0_N: J12.9(D0-) L21.2 R773.2
D0_P: J12.7(D0+) L21.3 R772.2
D1_N: J12.6(D1-) L20.2 R771.2
D1_P: J12.4(D1+) L20.3 R770.2
D2_N: J12.3(D2-) L19.2 R769.2
D2_P: J12.1(D2+) L19.3 R768.2
DFP_BACKLIGHT: J17.1 R235.2 ; also on sheet 29
DFP_BL_PWM: J17.3 R234.2 ; also on sheet 29
DFP_D0: U21.5(1B2) U37.94(D0)
DFP_D1: U21.11(2B2) U37.93(D1)
DFP_D2: U23.5(1B2) U37.92(D2)
DFP_D3: U23.11(2B2) U37.91(D3)
DFP_D4: U26.5(1B2) U37.90(D4)
DFP_D5: U26.11(2B2) U37.89(D5)
DFP_D6: U28.5(1B2) U37.86(D6)
DFP_D7: U28.11(2B2) U37.85(D7)
DFP_D8: U22.5(1B2) U37.84(D8)
DFP_D9: U22.11(2B2) U37.83(D9)
DFP_D10: U24.5(1B2) U37.82(D10)
DFP_D11: U24.11(2B2) U37.81(D11)
DFP_DCLK: R225.2 U27.11(2B2) U37.87(CLKIN_P)
DFP_DE: R223.2 U27.5(1B2) U37.76(DE)
DFP_HSYNC: U25.6(2Y) U37.75(HSYNC)
DFP_INT_N: R221.1 U37.21(MSEN) ; also on sheet 29
DFP_MODE: Q6.1(G) ; also on sheet 29
DFP_RST_N: R222.1 U37.22(~{PD}) ; also on sheet 29
DFP_VSYNC: U25.11(4Y) U37.74(VSYNC)
DIU_HSYNC: U25.2(1A) U25.5(2A) ; also on sheet 7
DIU_VSYNC: U25.9(3A) U25.12(4A) ; also on sheet 7
DVI_D0: U21.6(1B1) U35.63(D0)
DVI_D1: U21.10(2B1) U35.62(D1)
DVI_D2: U23.6(1B1) U35.61(D2)
DVI_D3: U23.10(2B1) U35.60(D3)
DVI_D4: U26.6(1B1) U35.59(D4)
DVI_D5: U26.10(2B1) U35.58(D5)
DVI_D6: U28.6(1B1) U35.55(D6)
DVI_D7: U28.10(2B1) U35.54(D7)
DVI_D8: U22.6(1B1) U35.53(D8)
DVI_D9: U22.10(2B1) U35.52(D9)
DVI_D10: U24.6(1B1) U35.51(D10)
DVI_D11: U24.10(2B1) U35.50(D11)
DVI_DCLK: U27.10(2B1) U35.57(XCLK+)
DVI_DE: R209.2 U27.6(1B1) U35.2(DE)
DVI_HSYNC: U25.3(1Y) U35.4(H)
DVI_INT_N: R216.2 U35.7(GPIO1/HPINT) ; also on sheet 29
DVI_RST_N: R217.2 U35.13(~{RESET}) ; also on sheet 29
DVI_TDC0_N: L21.1 R773.1 U35.21(TDC0-) U36.12(TMDS_D0-) U36.27(TMDSO_D0-)
DVI_TDC0_P: L21.4 R772.1 U35.22(TDC0+) U36.10(TMDS_D0+) U36.29(TMDSO_D0+)
DVI_TDC1_N: L20.1 R771.1 U35.24(TDC1-) U36.9(TMDS_D1-) U36.30(TMDSO_D1-)
DVI_TDC1_P: L20.4 R770.1 U35.25(TDC1+) U36.7(TMDS_D1+) U36.32(TMDSO_D1+)
DVI_TDC2_N: L19.1 R769.1 U35.27(TDC2-) U36.6(TMDS_D2-) U36.33(TMDSO_D2-)
DVI_TDC2_P: L19.4 R768.1 U35.28(TDC2+) U36.4(TMDS_D2+) U36.35(TMDSO_D2+)
DVI_TLC_N: L22.1 R775.1 U35.31(TLC-) U36.15(TMDS_CK-) U36.24(TMDSO_CK-)
DVI_TLC_P: L22.4 R774.1 U35.30(TLC+) U36.13(TMDS_CK+) U36.26(TMDSO_CK+)
DVI_VSYNC: R211.2 U25.8(3Y) U35.5(V)
EARTH: C345.2 C347.2 C353.2 J9.10 J9.20 J9.21 J9.22 J12.20(MH1) J12.21(MH2) J12.22(MH3) J12.23(MH4) J19.27 J19.28 ; also on sheet 10 20 21 22 23 26 37
EC1_GTXCLK: U42.22(TXC) ; also on sheet 8
EC1_INT_N: R262.2 ; also on sheet 7
EC1_LED0: R259.1 R274.1 U42.34(LED0/PHY_AD0)
EC1_LED1: R260.1 R275.1 U42.35(LED1/PHY_AD1)
EC1_MDI0_N: T1.11 U42.2(MDI-[0])
EC1_MDI0_P: T1.12 U42.1(MDI+[0])
EC1_MDI1_N: T1.8 U42.5(MDI-[1])
EC1_MDI1_P: T1.9 U42.4(MDI+[1])
EC1_MDI2_N: T1.5 U42.8(MDI-[2])
EC1_MDI2_P: T1.6 U42.7(MDI+[2])
EC1_MDI3_N: T1.2 U42.11(MDI-[3])
EC1_MDI3_P: T1.3 U42.10(MDI+[3])
EC1_MDX0_N: J19.B2 T1.14
EC1_MDX0_P: J19.B1 T1.13
EC1_MDX1_N: J19.B6 T1.17
EC1_MDX1_P: J19.B3 T1.16
EC1_MDX2_N: J19.B5 T1.20
EC1_MDX2_P: J19.B4 T1.19
EC1_MDX3_N: J19.B8 T1.23
EC1_MDX3_P: J19.B7 T1.22
EC1_PME_N: R264.2 ; also on sheet 7
EC1_REFCLK: R258.2 ; also on sheet 8
EC1_RST_N: R265.2 U42.29(~{PHYRST}) ; also on sheet 29
EC1_RXCLK: R250.1 ; also on sheet 8
EC1_RXCTL: R256.1 R273.1 ; also on sheet 8
EC1_RXD0: R251.1 R269.1 ; also on sheet 8
EC1_RXD1: R253.1 R270.1 ; also on sheet 8
EC1_RXD2: R254.1 R271.1 ; also on sheet 8
EC1_RXD3: R255.1 R272.1 ; also on sheet 8
EC1_RXDLY: R276.1 U42.32(LED2/RXDLY)
EC1_TXCTL: U42.27(TXCTL) ; also on sheet 8
EC1_TXD0: U42.23(TXD0) ; also on sheet 8
EC1_TXD1: U42.24(TXD1) ; also on sheet 8
EC1_TXD2: U42.25(TXD2) ; also on sheet 8
EC1_TXD3: U42.26(TXD3) ; also on sheet 8
EMI1_MDC_SLP: U42.30(MDC) ; also on sheet 8
EMI1_MDIO_SLP: U42.31(MDIO) ; also on sheet 8
EVDD: C136.1 U1.L8(EVDD1) ; also on sheet 6 35
I2C1_SCL: U32.6(SCL) U35.15(SPC) U37.59(I2CCLK/DDREN) ; also on sheet 7
I2C1_SCL_SLP: U31.6(SCL) U34.8(SCLK) ; also on sheet 3 7 31 32
I2C1_SDA: U32.5(SDA) U35.14(SPD) U37.60(I2CDAT/DSEL) ; also on sheet 7
I2C1_SDA_SLP: U31.5(SDA) U34.7(SDATA) ; also on sheet 3 7 31 32
I2C2_HDMI_SCL: R205.1 U36.17(DDC_CLK_IN) ; also on sheet 7
I2C2_HDMI_SDA: R208.1 U36.18(DDC_DAT_IN) ; also on sheet 7
ISO_DE: J42.4 U40.10(ISODE)
ISO_RXD_TXD_N: J42.3 R243.1 R244.2 U40.13(B)
ISO_RXD_TXD_P: J18.2 J42.2 R242.1 U40.12(A)
LVDS0_N: J13.5 U37.50(A0M)
LVDS0_P: J13.6 U37.49(A0P)
LVDS1_N: J13.8 U37.47(A1M)
LVDS1_P: J13.9 U37.46(A1P)
LVDS2_N: J13.11 U37.45(A2M)
LVDS2_P: J13.12 U37.44(A2P)
LVDS3_N: J13.17 U37.39(A3M)
LVDS3_P: J13.18 U37.38(A3P)
LVDS_CLK_N: J13.14 U37.42(CLK1M)
LVDS_CLK_P: J13.15 U37.41(CLK1P)
PROFI_MUX_CFG: U39.1(S) ; also on sheet 29
PROFI_PWR_OUT: L3.1 R236.2 U38.4(+VOUT)
QE_MUX_CFG0: U21.14(S0) U22.14(S0) U23.14(S0) U24.14(S0) U26.14(S0) U27.14(S0) U28.14(S0) ; also on sheet 29
QE_MUX_CFG1: U21.2(S1) U22.2(S1) U23.2(S1) U24.2(S1) U26.2(S1) U27.2(S1) U28.2(S1) ; also on sheet 29
QED_D0: U1.U2(TDMA_RXD) U21.7(1A)
QED_D1: U1.U1(TDMA_RSYNC) U21.9(2A)
QED_D2: U1.T1(TDMA_TXD) U23.7(1A)
QED_D3: U1.R1(TDMA_TSYNC) U23.9(2A)
QED_D4: U1.R2(TDMA_RQ) U26.7(1A)
QED_D5: U1.U4(TDMB_RXD) U26.9(2A)
QED_D6: U1.T3(TDMB_RSYNC) U28.7(1A)
QED_D7: U1.T4(TDMB_TXD) U28.9(2A)
QED_D8: U1.R3(TDMB_TSYNC) U22.7(1A)
QED_D9: U1.R4(TDMB_RQ) U22.9(2A)
QED_D10: U1.P4(CLK09) U24.7(1A)
QED_D11: U1.P3(CLK10) U24.9(2A)
QED_D12: U1.N4(CLK11) U27.7(1A)
QED_D13: R170.2 U27.9(2A)
RS232_CTS1: C280.1 FB11.2 J9.8 U33.2
RS232_CTS2: C289.1 FB15.2 J9.18 U33.1
RS232_RTS1: C281.1 FB10.2 J9.7 U33.4
RS232_RTS2: C290.1 FB14.2 J9.17 U33.7
RS232_RXD1: C282.1 FB9.2 J9.2 U33.5
RS232_RXD2: C291.1 FB13.2 J9.12 U33.8
RS232_TXD1: C283.1 FB8.2 J9.3 U33.3
RS232_TXD2: C292.1 FB12.2 J9.13 U33.6
RTC_INT_N: R190.1 U31.7(SQ~{WINT}) ; also on sheet 7
SENSEGND: TP18.1(TP) U1.G20(SENSEGND)
SENSEGNDC: TP16.1(TP) U1.AB10(SENSEGNDC)
SENSEVDD: TP17.1(TP) U1.G19(SENSEVDD) ; also on sheet 32
SENSEVDDC: TP15.1(TP) U1.AB9(SENSEVDDC) ; also on sheet 32
SPI_CLK: R200.2 ; also on sheet 6
SPI_MISO: R201.2 ; also on sheet 6
SPI_MOSI: R202.2 ; also on sheet 6
TDMA_RCK_CLK8_12: J11.21 U27.13(2B4)
TDMA_RQ: J11.3 U26.3(1B4)
TDMA_RSYNC: J11.11 U21.13(2B4)
TDMA_RXD: J11.13 U21.3(1B4)
TDMA_TCK_CLK9: J11.17 U24.3(1B4)
TDMA_TSYNC: J11.9 U23.13(2B4)
TDMA_TXD: J11.7 U23.3(1B4)
TDMB_RCK_CLK10: J11.29 U24.13(2B4)
TDMB_RQ: J11.24 U22.13(2B4)
TDMB_RSYNC: J11.18 U28.3(1B4)
TDMB_RXD: J11.1 U26.13(2B4)
TDMB_TCK_CLK11: J11.39 U27.3(1B4)
TDMB_TSYNC: J11.22 U22.3(1B4)
TDMB_TXD: J11.20 U28.13(2B4)
TDMR1_INT_N: J11.31 R197.2 ; also on sheet 29
TDMR2_INT_N: J11.33 R198.2 ; also on sheet 29
TDMR_PRS_N: J11.27 R196.2 ; also on sheet 29
TDMR_RST_N: J11.35 R199.2 U40.7(PV) ; also on sheet 29
TDMR_SLP_N: J11.25 ; also on sheet 29
TDMR_SPI_CS0_N: J11.32 ; also on sheet 6
TDMR_SPI_CS1_N: J11.34 ; also on sheet 6
TEMP_DIODE_N: R194.1 ; also on sheet 7
TEMP_DIODE_P: R193.1 ; also on sheet 7
THERM_ALERT_N: R192.1 U34.6(~{ALERT}/~{THERM2}) ; also on sheet 29
THERM_FAULT_N: R195.1 U34.4(~{THERM}) ; also on sheet 29
UART1_CTS_N: U29.9(R2-OUT) ; also on sheet 7
UART1_RTS_N: U29.10(T2-IN) ; also on sheet 7
UART1_RXD: U29.12(R1-OUT) ; also on sheet 7
UART1_TXD: U29.11(T1-IN) ; also on sheet 7
UART2_CTS_N: U30.9(R2-OUT) ; also on sheet 7
UART2_RTS_N: U30.10(T2-IN) ; also on sheet 7
UART2_RXD: U30.12(R1-OUT) ; also on sheet 7
UART2_TXD: U30.11(T1-IN) ; also on sheet 7
UC1_CDBRXER: R240.2 U26.4(1B3)
UC1_CTS_N: U21.12(2B3) U39.11(3B1)
UC1_RTS_N: U23.12(2B3) U39.14(4B1)
UC1_RXD: U21.4(1B3) U39.2(1B1)
UC1_TXD: U23.4(1B3) U39.5(2B1)
UC3_CDBRXER: R239.2 U22.12(2B3)
UC3_CTS_N: U28.4(1B3) U39.10(3B2)
UC3_RTS_N: U22.4(1B3) U39.13(4B2)
UC3_RXD: U26.12(2B3) U39.3(1B2)
UC3_TXD: U28.12(2B3) U39.6(2B2)
VCORE: C137.1 C138.1 C139.1 C140.1 C141.1 C142.1 C143.1 C145.1 C153.1 C154.1 C155.1 C156.1 C165.1 C166.1 C167.1 C168.1 C169.1 C171.1 C172.1 C173.1 C175.1 C176.1 C177.1 C178.1 C179.1 C180.1 C181.1 C182.1 C184.1 C185.1 C186.1 C187.1 C188.1 C189.1 C190.1 C191.1 C194.1 C195.1 C196.1 C197.1 C198.1 C199.1 C200.1 C201.1 C202.1 C203.1 C204.1 C205.1 C206.1 C207.1 C208.1 J8.2 U1.K15(VDD01) U1.K17(VDD02) U1.K19(VDD03) U1.L12(VDD04) U1.L14(VDD05) U1.L16(VDD06) U1.L18(VDD07) U1.L20(VDD08) U1.M9(VDD09) U1.M13(VDD10) U1.M15(VDD11) U1.M17(VDD12) U1.M19(VDD13) U1.N12(VDD14) U1.N14(VDD15) U1.N16(VDD16) U1.N18(VDD17) U1.N20(VDD18) U1.P9(VDD19) U1.P11(VDD20) U1.P13(VDD21) U1.P15(VDD22) U1.P17(VDD23) U1.P19(VDD24) U1.R12(VDD25) U1.R14(VDD26) U1.R16(VDD27) U1.R18(VDD28) U1.R20(VDD29) U1.T9(VDD30) U1.T13(VDD31) U1.T15(VDD32) U1.T17(VDD33) U1.T19(VDD34) U1.U14(VDD35) U1.U16(VDD36) U1.U18(VDD37) U1.U20(VDD38) U1.V9(VDD39) U1.V13(VDD40) U1.V15(VDD41) U1.V17(VDD42) U1.V19(VDD43) U1.W14(VDD44) U1.Y8(VDD45) U1.Y9(VDD46) U1.Y11(VDD47) ; also on sheet 32
VCORE_SLP: C218.1 C219.1 C220.1 C221.1 C226.1 C227.1 C228.1 C229.1 C230.1 C231.1 C232.1 C233.1 C234.1 FB5.2 U1.K11(VDDC01) U1.K13(VDDC02) U1.L10(VDDC03) U1.M11(VDDC04) U1.N10(VDDC05) U1.R10(VDDC06) U1.T11(VDDC07) U1.U10(VDDC08) U1.U12(VDDC09) U1.V11(VDDC10) U1.W10(VDDC11) U1.W12(VDDC12) ; also on sheet 32
XVDD: C193.2 C237.1 C238.1 C239.1 C240.1 C241.1 C242.1 C243.1 C244.1 U1.AC9(X1VDD1) U1.AC12(X1VDD2) U1.AC15(X1VDD3) U1.AC18(X1VDD4) U1.AC21(X1VDD5) ; also on sheet 8
N16870296: C345.1 R247.2 R248.2 R249.2 R252.2
N16870380: C339.2 C341.2 C342.2 C344.2 T1.1 T1.4 T1.7 T1.10
N16870836: C349.1 J19.B9 R259.2
N16870842: C348.1 J19.B11 R260.2
N17055310: C277.1 U29.2(V+)
N17055339: C279.1 U29.6(V-)
N17055373: C275.2 U29.1(C1+)
N17055376: C275.1 U29.3(C1-)
N17055394: C278.2 U29.4(C2+)
N17055396: C278.1 U29.5(C2-)
N17055419: R182.1 U29.14(T1-OUT)
N17055422: R183.1 U29.13(R1-IN)
N17055459: R185.1 U29.8(R2-IN)
N17055461: R184.1 U29.7(T2-OUT)
N17055495: FB8.1 R182.2
N17055507: FB9.1 R183.2
N17055527: FB10.1 R184.2
N17055529: FB11.1 R185.2
N17056698: C287.1 U30.2(V+)
N17056714: C288.1 U30.6(V-)
N17056740: C284.2 U30.1(C1+)
N17056750: C284.1 U30.3(C1-)
N17056764: C286.2 U30.4(C2+)
N17056766: C286.1 U30.5(C2-)
N17056776: R186.1 U30.14(T1-OUT)
N17056778: R187.1 U30.13(R1-IN)
N17056796: R189.1 U30.8(R2-IN)
N17056798: R188.1 U30.7(T2-OUT)
N17056816: FB12.1 R186.2
N17056834: FB13.1 R187.2
N17056844: FB14.1 R188.2
N17056846: FB15.1 R189.2
N17424508: C294.1 J10.1 R191.1
N17424523: R191.2 U31.3(VBACKUP)
N17424557: U31.2(X2) Y1.4
N17424571: U31.1(X1) Y1.1
N17424740: C296.2 R193.2 U34.2(D+)
N17424742: C296.1 R194.2 U34.3(D-)
N17433404: R226.2 U37.88(CLKIN_N)
N17437095: R210.1 R220.1 U35.8(GPIO0)
N17437909: D4.2 R220.2
N17484067: J12.13(CE_Remote) U36.23(CE_REMOTE_OUT)
N17484070: J12.15(DDC_CLK) R204.1 U36.22(DDC_CLK_OUT)
N17484079: J12.16(DDC_DATA) R203.1 U36.21(DDC_DAT_OUT)
N17484088: J12.19(HP_DET) R215.2 U36.20(HOTPLUG_DET_OUT)
N17484885: C304.1 U36.37(ESD_BYP)
N17497489: R207.1 R210.2 U36.16(CE_REMOTE_IN)
N17497523: R206.1 U35.9(HPDET) U36.19(HOTPLUG_DET_IN)
N17498064: R212.1 U35.35(ISET)
N17498075: R213.1 U35.19(VSWING)
N17500984: R219.2 U35.10(AS)
N17501134: C306.2 R214.2 R218.2 U35.3(VREF) U35.56(XCLK-)
N17551792: J18.1 R243.2
N17554945: U39.4(1A) U40.3(R)
N17554954: R241.1 U39.7(2A) U40.6(D)
N17555031: R245.2 U40.4(~{RE})
N17555276: U39.12(4A) U41.2(I)
N17555960: R246.1 U40.5(DE) U41.4(O)
N17588753: C343.2 R250.2 U42.19(RXC)
N17588764: R251.2 U42.14(RXD0/SELRGV)
N17588767: R253.2 U42.16(RXD1/TXDLY)
N17588769: R254.2 U42.17(RXD2/AN0)
N17588771: R255.2 U42.18(RXD3/AN1)
N17588772: R256.2 U42.13(RXCTL/PHY_AD2)
N17588858: R262.1 U42.20(~{INT})
N17588875: C350.1 U42.42(CKXTAL1) Y2.1
N17588878: C351.1 U42.43(CKXTAL2) Y2.3
N17588897: C346.1 R258.1 U42.46(CLK125)
N17588905: R264.1 U42.33(~{PME})
N17588927: L4.1 R266.1 U42.48(REG_OUT)
N17588950: C352.1 R266.2
N17589014: R268.2 U42.39(RSET)
N17593781: R247.1 T1.15
N17593783: R248.1 T1.18
N17593791: R249.1 T1.21
N17593793: R252.1 T1.24
N17748293: J13.19 J14.1 R224.2
N17749501: J15.1 R227.1
N17749602: J13.20 J15.2 Q6.3(D)
N18257321: FB46.1 U36.38(5V_OUT)
N18551266: R263.2 U42.38(ENSWREG)
N18720737: R170.1 U1.M4(CLK12)
N18753359: R229.2 U37.18(R_FB)
N18753377: R230.2 U37.19(R_FDE)
N18753428: R232.2 U37.24(BAL)
N18753501: R231.2 U37.23(DUAL)
N18753516: R228.2 U37.12(PRE)
N19119205: F1.2 J16.2 R233.2
N21754633: J11.28 R200.1
N21754692: J11.36 R201.1
N21754708: J11.38 R202.1

Not connected (* = marked no-connect by the designer): J9 1* 4* 6* 9* 11* 14* 16* 19*; J11 8*; J12 14(NC)*; U1 AA6(NC08)* AA7(NC09)* AA8(NC10)* AA9(NC11)* AA10(NC12)* AB8(NC13)* AB11(NC14)* AB12(NC15)* AG28(NC_DET)* AH27(DEV_DET)* F10(TH_TPA)* G6(SPARE1)* G17(NC01)* H6(SPARE2)* J6(SPARE3)* N6(NC02)* T6(NC03)* U6(NC04)* V6(NC05)* W6(NC06)* Y6(NC07)*; U24 4(1B3)* 12(2B3)*; U27 4(1B3)* 12(2B3)*; U35 16(NC1)* 37(G)* 38(R)* 39(B)* 41(NC2)* 42(NC3)* 43(NC4)* 44(NC5)* 46(NC6)* 47(VSYNC)* 48(HSYNC)*; U37 26(CLK2P)* 27(CLK2M)* 28(A7P)* 29(A7M)* 31(A6P)* 32(A6M)* 33(A5P)* 34(A5M)* 36(A4P)* 37(A4M)* 55(RSVD3)* 73(TST2)*; U39 9(3A)*; U40 11(NC1)* 14(NC2)*; U41 1(NC)*; U42 12(NC)*

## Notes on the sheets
sheet 11
- T104X QE-TDM/DIU MUX/DEMUX
sheet 12
- T104X POWER SUPPLY
- USB_SVDD supply must ramp before or after the
  USB_HVDD and USB_OVDD supplies have ramped.
- Though hole test points, route as differential signals
- LABEL = PROG_SFP
- LABEL = PROG_MTR
- LABEL = FA_VDD
sheet 13
- T104X PLL FILTERs and GROUND
- DDR4 UDIMM VDD DECOUPLING
sheet 14
- T104X DUART and I2C DEVICE INTERFACE
- RTC
- I2C EEPROM
- I2C ADR = 0x68
- I2C ADDR = 0x50
- For RS232 ESD protection, place close to connector
- I2C THERMAL MONITOR
- I2C ADDR = 0x4C
sheet 15
- TDM RISER INTERFACE
- TDM RISER CARD CONNECTOR
- T104X DVDD: 3.3V
sheet 16
- HDMI DISPLAY INTERFACE
- I2C ADDR = 0x75
- LABEL = DVI SEL
sheet 17
- LVDS PANEL INTERFACE
- I2C ADDR = 0x38
- 100 ohms
  DIFF PAIRs
- LABEL = FLIP
- LABEL = PNLFMT
- No pre-emphasis
- DCLK Falling-Edge
- DE Active-High
- Since 12b input
- Unbalanced LVDS Outputs
- LABEL = BACKLIGHT
- LABEL = BACKCTL
sheet 18
- PROFIBUS INTERFACE
- LOW ESR
- Place Close to
  MEV1S0505DC
sheet 19
- RGMII ETHERNET PORT 1
- 100 ohms
  DIFF PAIRs
- RGMII PHY POWER-ON STRAPPINGs
- SELRGV
- TXDLY
- 2.5V
- AN0
- NWay, advertize all capability
- AN1
- PHY_AD2
- PHY_AD0
- PHY ADDR = 0x04
- PHY_AD1
- RXDLY
